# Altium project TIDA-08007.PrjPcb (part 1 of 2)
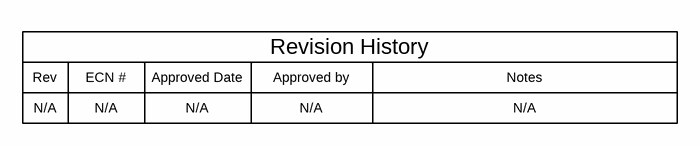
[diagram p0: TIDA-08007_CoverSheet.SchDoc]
CopyrightYear: 2019; PCB_Layout: Tessolve; PCB_Rev: A; PRJ_Customer: Public Release; PRJ_Engineer: Jake Pulliam; PRJ_Number: TIDA-080007; PRJ_Title: TIDA-080007; SCH_Rev: A; TechSupport: http://www.ti.com/support; TID: TIDA-080007
10 sheets, 292 parts. Net scope: flat (ports and power ports of the same name join across sheets).
Board file: TIDA-08007.PcbDoc
Sheets:
  TIDA-08007_CoverSheet.SchDoc
  TIDA-08007_DLPC230Interface.SchDoc
  TIDA-08007_VideoInterface.SchDoc
  TIDA-08007_DLPC230Power.SchDoc
  TIDA-08007_DLPC230GPIO.SchDoc
  TIDA-08007_DMDInterface.SchDoc
  TIDA-08007_DMDPower.SchDoc
  TIDA-08007_TPS99000Interface.SchDoc
  TIDA-08007_Power.SchDoc
  TIDA-08007_Hardware.SchDoc

## Sheet TIDA-08007_CoverSheet.SchDoc: Cover Page
size 431 x 279 mm; Date: Not shown in title block; ApprovedBy: Not shown in title block; CheckedBy: Not shown in title block; Author: Not shown in title block; CompanyName: Not shown in title block; DrawnBy: Jake Pulliam; Engineer: Jake Pulliam; Organization: Not shown in title block; Address1: Not shown in title block; Address2: Not shown in title block; Address3: Not shown in title block; Address4: Not shown in title block; DocumentNumber: 1; Revision: Use project parameter SCH_Rev; SheetNumber: 1; SheetTotal: 10; PageSetup: Record=PageOptions¦CenterHorizontal=True¦CenterVertical=True¦PrintScale=1.00¦XCorrection=1.00¦YCorrection=1.00¦PrintKind=0¦BorderSize=5000000¦LeftOffset=0¦BottomOffset=0¦Orientation=2¦PaperLength=1000¦PaperWidth=1000¦Scale=100¦PaperSource=15¦PrintQuality=600¦MediaType=1¦DitherType=10¦PaperKind=Letter¦PrintScaleMode=1

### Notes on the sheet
- Rev
- N/A
- ECN #
- Approved Date
- Approved by
- Revision History
- Notes

## Sheet TIDA-08007_DLPC230Interface.SchDoc: DLPC230 Host Interface
size 431 x 279 mm; Date: Not shown in title block; ApprovedBy: Not shown in title block; CheckedBy: Not shown in title block; Author: Not shown in title block; CompanyName: Not shown in title block; DrawnBy: Jake Pulliam; Engineer: Not shown in title block; Organization: Not shown in title block; Address1: Not shown in title block; Address2: Not shown in title block; Address3: Not shown in title block; Address4: Not shown in title block; DocumentNumber: 2; Revision: Use project parameter SCH_Rev; SheetNumber: 2; SheetTotal: 10; PageSetup: Record=PageOptions¦CenterHorizontal=True¦CenterVertical=True¦PrintScale=1.00¦XCorrection=1.00¦YCorrection=1.00¦PrintKind=0¦BorderSize=5000000¦LeftOffset=0¦BottomOffset=0¦Orientation=2¦PaperLength=1000¦PaperWidth=1000¦Scale=100¦PaperSource=15¦PrintQuality=600¦MediaType=1¦DitherType=10¦PaperKind=Letter¦PrintScaleMode=1
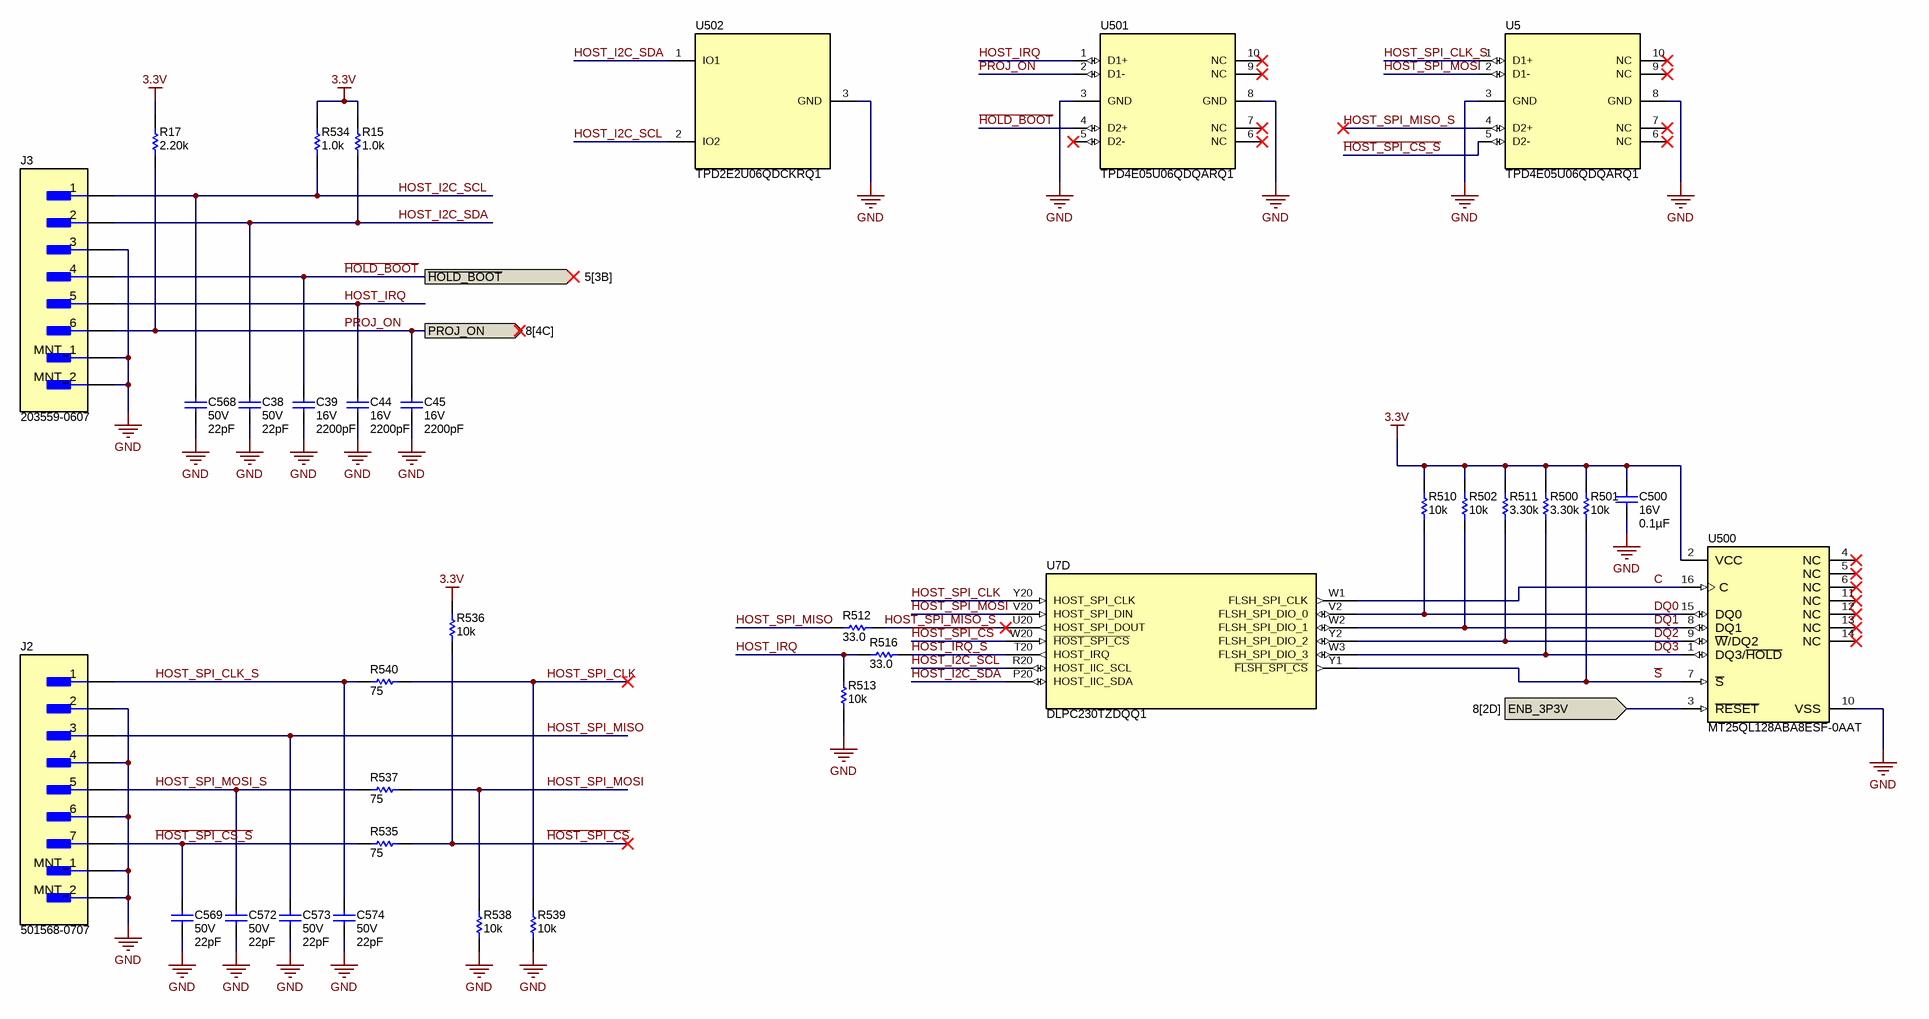
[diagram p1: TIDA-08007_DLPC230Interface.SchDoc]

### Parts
C38  VDC_V: 50V  ValueDisplayed: 22pF  [0402]  (hidden comment: CGA2B2NP01H220J050BA)
C39  VDC_V: 16V  ValueDisplayed: 2200pF  [0402]  (hidden comment: GRM155R71C222KA01D)
C44  VDC_V: 16V  ValueDisplayed: 2200pF  [0402]  (hidden comment: GRM155R71C222KA01D)
C45  VDC_V: 16V  ValueDisplayed: 2200pF  [0402]  (hidden comment: GRM155R71C222KA01D)
C500  VDC_V: 16V  ValueDisplayed: 0.1µF  [0402]  (hidden comment: GCM155R71C104JA55D)
C568  VDC_V: 50V  ValueDisplayed: 22pF  [0402]  (hidden comment: CGA2B2NP01H220J050BA)
C569  VDC_V: 50V  ValueDisplayed: 22pF  [0402]  (hidden comment: CGA2B2NP01H220J050BA)
C572  VDC_V: 50V  ValueDisplayed: 22pF  [0402]  (hidden comment: CGA2B2NP01H220J050BA)
C573  VDC_V: 50V  ValueDisplayed: 22pF  [0402]  (hidden comment: CGA2B2NP01H220J050BA)
C574  VDC_V: 50V  ValueDisplayed: 22pF  [0402]  (hidden comment: CGA2B2NP01H220J050BA)
J2  501568-0707  [FP-501568-0707_HDR7-MFG]
J3  203559-0607  [FP-203559-0607_HDR6-MFG]
R15  ValueDisplayed: 1.0k  [0402]  (hidden comment: ERJ-2GEJ102X)
R17  ValueDisplayed: 2.20k  [0402]  (hidden comment: ERJ-2RKF2201X)
R500  ValueDisplayed: 3.30k  [0402]  (hidden comment: ERJ-2RKF3301X)
R501  ValueDisplayed: 10k  [0402]  (hidden comment: ERJ-2GEJ103X)
R502  ValueDisplayed: 10k  [0402]  (hidden comment: ERJ-2GEJ103X)
R510  ValueDisplayed: 10k  [0402]  (hidden comment: ERJ-2GEJ103X)
R511  ValueDisplayed: 3.30k  [0402]  (hidden comment: ERJ-2RKF3301X)
R512  ValueDisplayed: 33.0  [0402]  (hidden comment: ERJ-2RKF33R0X)
R513  ValueDisplayed: 10k  [0402]  (hidden comment: ERJ-2GEJ103X)
R516  ValueDisplayed: 33.0  [0402]  (hidden comment: ERJ-2RKF33R0X)
R534  ValueDisplayed: 1.0k  [0402]  (hidden comment: ERJ-2GEJ102X)
R535  ValueDisplayed: 75  [0805_HV]  (hidden comment: ERJ-6GEYJ750V)
R536  ValueDisplayed: 10k  [0402]  (hidden comment: ERJ-2GEJ103X)
R537  ValueDisplayed: 75  [0805_HV]  (hidden comment: ERJ-6GEYJ750V)
R538  ValueDisplayed: 10k  [0402]  (hidden comment: ERJ-2GEJ103X)
R539  ValueDisplayed: 10k  [0402]  (hidden comment: ERJ-2GEJ103X)
R540  ValueDisplayed: 75  [0805_HV]  (hidden comment: ERJ-6GEYJ750V)
U5  TPD4E05U06QDQARQ1  [DQA0010A]
U7  DLPC230TZDQQ1  [ZDQ0324]  (part D of 9)
U500  MT25QL128ABA8ESF-0AAT  [FP-MT25QL128ABA8ESF-0AAT_SOP2-16-MFG]
U501  TPD4E05U06QDQARQ1  [DQA0010A]
U502  TPD2E2U06QDCKRQ1  [DCK0003A_N]

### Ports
ENB_3P3V (in, see 8[2D]), PROJ_ON (out, see 8[4C]), ~{HOLD_BOOT} (out, see 5[3B])

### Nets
3.3V: C500.1 R15.2 R17.2 R500.2 R501.2 R502.2 R510.2 R511.2 R534.2 R536.2 U500.2(VCC)
GND: C38.2 C39.2 C44.2 C45.2 C500.2 C568.2 C569.2 C572.2 C573.2 C574.2 J2.2 J2.4 J2.6 J2.8(MNT_1) J2.9(MNT_2) J3.3 J3.7(MNT_1) J3.8(MNT_2) R513.1 R538.1 R539.1 U5.3(GND) U5.8(GND) U500.10(VSS) U501.3(GND) U501.8(GND) U502.3(GND)
~{HOLD_BOOT}: C39.1 J3.4 U501.4(D2+) ; port ~{HOLD_BOOT}
~{HOST_SPI_CS}: R535.2 R536.1 U7.W20(~{HOST_SPI_CS})
~{HOST_SPI_CS_S}: C569.1 J2.7 R535.1 U5.5(D2-)
~{S}: R501.1 U7.Y1(~{FLSH_SPI_CS}) U500.7(~{S})
C: U7.W1(FLSH_SPI_CLK) U500.16(C)
DQ0: R510.1 U7.V2(FLSH_SPI_DIO_0) U500.15(DQ0)
DQ1: R502.1 U7.W2(FLSH_SPI_DIO_1) U500.8(DQ1)
DQ2: R511.1 U7.Y2(FLSH_SPI_DIO_2) U500.9(~{W}/DQ2)
DQ3: R500.1 U7.W3(FLSH_SPI_DIO_3) U500.1(DQ3/~{HOLD})
ENB_3P3V: U500.3(~{RESET}) ; port ENB_3P3V
HOST_I2C_SCL: C568.1 J3.1 R534.1 U7.R20(HOST_IIC_SCL) U502.2(IO2)
HOST_I2C_SDA: C38.1 J3.2 R15.1 U7.P20(HOST_IIC_SDA) U502.1(IO1)
HOST_IRQ: C44.1 J3.5 R513.2 R516.1 U501.1(D1+)
HOST_IRQ_S: R516.2 U7.T20(HOST_IRQ)
HOST_SPI_CLK: R539.2 R540.2 U7.Y20(HOST_SPI_CLK)
HOST_SPI_CLK_S: C574.1 J2.1 R540.1 U5.1(D1+)
HOST_SPI_MISO: C573.1 J2.3 R512.1
HOST_SPI_MISO_S: R512.2 U5.4(D2+) U7.U20(HOST_SPI_DOUT)
HOST_SPI_MOSI: R537.2 R538.2 U5.2(D1-) U7.V20(HOST_SPI_DIN)
HOST_SPI_MOSI_S: C572.1 J2.5 R537.1
PROJ_ON: C45.1 J3.6 R17.1 U501.2(D1-) ; port PROJ_ON

Not connected (* = marked no-connect by the designer): U5 6(NC)* 7(NC)* 9(NC)* 10(NC)*; U500 4(NC)* 5(NC)* 6(NC)* 11(NC)* 12(NC)* 13(NC)* 14(NC)*; U501 5(D2-)* 6(NC)* 7(NC)* 9(NC)* 10(NC)*

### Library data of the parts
C38 C568 C569 C572-C574 = CMP-0006311-2: CAP, CERM, 22 pF, 50 V, +/- 5%, C0G/NP0, AEC-Q200 Grade 1, 0402; Manufacturer: TDK; TaMin_C: -55°C; Polarized: N; SizeAreaWB_mm2: 3; Value1: Unknown; U/M: EA; Value: 22pF; TaMax_C: 125°C; SizeZ_mm: 0.6; SizeX_mm: 1; SizeY_mm: 0.5; AEC Qualified: Y; AEC Category: Q200
C39 C44 C45 = CMP-0006646-2: CAP, CERM, 2200 pF, 16 V, +/- 10%, X7R, 0402; Manufacturer: MuRata; TaMin_C: -55°C; Polarized: N; SizeAreaWB_mm2: 3; Value1: Unknown; U/M: EA; Value: 2200pF; TaMax_C: 125°C; SizeZ_mm: 0.6; SizeX_mm: 1; SizeY_mm: 0.5; Cap_F: 2.2nF; AEC Category: Q200
C500 = CMP-0080702-1: CAP, CERM, 0.1 µF, 16 V,+/- 5%, X7R, AEC-Q200 Grade 1, 0402; Manufacturer: MuRata; Cap_F: 100nF; SizeAreaWB_mm2: 3; SizeArea_mm2: 0.5; AEC Qualified: Y; AEC Category: Q200; Value: 0.1uF; TaMax_C: 125°C; SizeZ_mm: 0.6; AEC Grade: 1; Polarized: N; TaMin_C: -55°C; U/M: EA
J2 = CMP-0087313-1: CONN HEADER 1MM 7POS SMD R/A; Manufacturer: Molex; Voltage_V: 50V; Row_Count: 1; ContactFinish: Tin,Nickel; Current_A: 1A
J3 = CMP-0087314-1: CONN HEADER SMD R/A 6POS 1MM; Manufacturer: Molex; Current_A: 1A; Row_Count: 1; Voltage_V: 50V; ContactFinish: Gold,Nickel
R15 R534 = CMP-0078193-1: RES, 1.0 k, 5%, 0.1 W, AEC-Q200 Grade 0, 0402; Manufacturer: Panasonic; Value_Code: 1k00; SizeArea_mm2: 0.5; AEC Qualified: Y; AEC Category: Q200; Res_ohm: 1k; Value: 1.0k; SizeZ_mm: 0.6; Green_REACh: Passed; EIA_Code: E24; TempCo: 200 ppm/C; AEC Grade: 0; Power_W: 100mW; VDC_V: 50V; Value2: 0.1W; Green_Lifecycle: Active; U/M: EA; SizeX_mm: 1
R17 = CMP-0026681-1: RES, 2.20 k, 1%, 0.1 W, 0402; Manufacturer: Panasonic; Power_W: 100mW; TempCo: 100 ppm/C; Value_Code: 2k20; U/M: EA; Value: 2.20k; Res_ohm: 2.2k; SizeX_mm: 1; SizeY_mm: 0.5; SizeZ_mm: 0.6; Value2: 0.1W; VDC_V: 50V; AEC Category: Q200
R500 R511 = CMP-0026695-1: RES, 3.30 k, 1%, 0.1 W, AEC-Q200 Grade 0, 0402; Manufacturer: Panasonic; Power_W: 100mW; TempCo: 100 ppm/C; Value_Code: 3k30; U/M: EA; Value: 3.30k; Res_ohm: 3.3k; SizeX_mm: 1; SizeY_mm: 0.5; SizeZ_mm: 0.6; Value2: 0.1W; AEC Qualified: Y; VDC_V: 50V; AEC Grade: 0; AEC Category: Q200
R501 R502 R510 R513 R536 R538 R539 = CMP-0026994-4: RES, 10 k, 5%, 0.1 W, AEC-Q200 Grade 0, 0402; Manufacturer: Panasonic; Power_W: 100mW; TempCo: 200 ppm/C; Value_Code: 10k0; U/M: EA; Value: 10k; EIA_Code: E24; SizeX_mm: 1; SizeY_mm: 0.5; SizeZ_mm: 0.6; Value2: 0.1W; AEC Qualified: Y; VDC_V: 50V; AEC Grade: 0; AEC Category: Q200
R512 R516 = CMP-0026696-1: RES, 33.0, 1%, 0.1 W, 0402; Manufacturer: Panasonic; Power_W: 100mW; TempCo: 100 ppm/C; Value_Code: 33R0; U/M: EA; Value: 33.0; Res_ohm: 33; SizeX_mm: 1; SizeY_mm: 0.5; SizeZ_mm: 0.6; Value2: 0.1W; VDC_V: 50V; AEC Category: Q200
R535 R537 R540 = CMP-0020766-3: RES, 75, 5%, 0.125 W, AEC-Q200 Grade 0, 0805; Manufacturer: Panasonic; Power_W: 125mW; TempCo: 200 ppm/C; Value_Code: 75R0; Value: 75; EIA_Code: E24; SizeX_mm: 2; SizeY_mm: 1.25; SizeZ_mm: 1.45; Value2: 0.125W; SizeArea_mm2: 2.5; AEC Qualified: Y; VDC_V: 150V; AEC Category: Q200; AEC Grade: 0; SizeAreaWB_mm2: 6.75
U5 U501 = CMP-0073599-3: Automotive 4-Channel ESD Protection Solution for SuperSpeed (up to 5 Gbps) Interface, DQA0010A (USON-10); Manufacturer: Texas Instruments; SizeZ_mm: 0.55; SizeX_mm: 1.0; SizeY_mm: 2.5; CompType: IC; SizeAreaWB_mm2: 7.0; AEC Category: Q200; AEC Qualified: Y
U7 = CMP-0750177-3: DLP® Automotive DMD Controller for DLP553x-Q1 Chipset, ZDQ0324 (BGA-324); Manufacturer: Texas Instruments; SizeAreaWB_mm2: 625; SizeArea_mm2: 529; SizeX_mm: 23; AEC Qualified: Y; CompType: IC; AEC Category: Q200; SizeZ_mm: 2.352
U500 = CMP-0086504-1: FLASH - NOR Memory IC 128Mb (16M x 8) SPI 133MHz  16-SOP2; Manufacturer: Micron; SizeZ_mm: 2.65mm
U502 = CMP-0073595-1: Automotive Dual-Channel High-Speed ESD Protection Device, DCK0003A (SOT-SC70-3); Alternate Manufacturer: Texas Instruments; SizeAreaWB_mm2: 9.3; U/M: EA; SizeZ_mm: 1.1; SizeX_mm: 2.1; SizeY_mm: 2.0; SizeArea_mm2: 4.2; CompType: IC

## Sheet TIDA-08007_VideoInterface.SchDoc: DLPC230 OpenLDI Interface
size 431 x 279 mm; Date: Not shown in title block; ApprovedBy: Not shown in title block; CheckedBy: Not shown in title block; Author: Not shown in title block; CompanyName: Not shown in title block; DrawnBy: Jake Pulliam; Engineer: Not shown in title block; Organization: Not shown in title block; Address1: Not shown in title block; Address2: Not shown in title block; Address3: Not shown in title block; Address4: Not shown in title block; DocumentNumber: 3; Revision: Use project parameter SCH_Rev; SheetNumber: 3; SheetTotal: 10; PageSetup: Record=PageOptions¦CenterHorizontal=True¦CenterVertical=True¦PrintScale=1.00¦XCorrection=1.00¦YCorrection=1.00¦PrintKind=0¦BorderSize=5000000¦LeftOffset=0¦BottomOffset=0¦Orientation=2¦PaperLength=1000¦PaperWidth=1000¦Scale=100¦PaperSource=15¦PrintQuality=600¦MediaType=1¦DitherType=10¦PaperKind=Letter¦PrintScaleMode=1
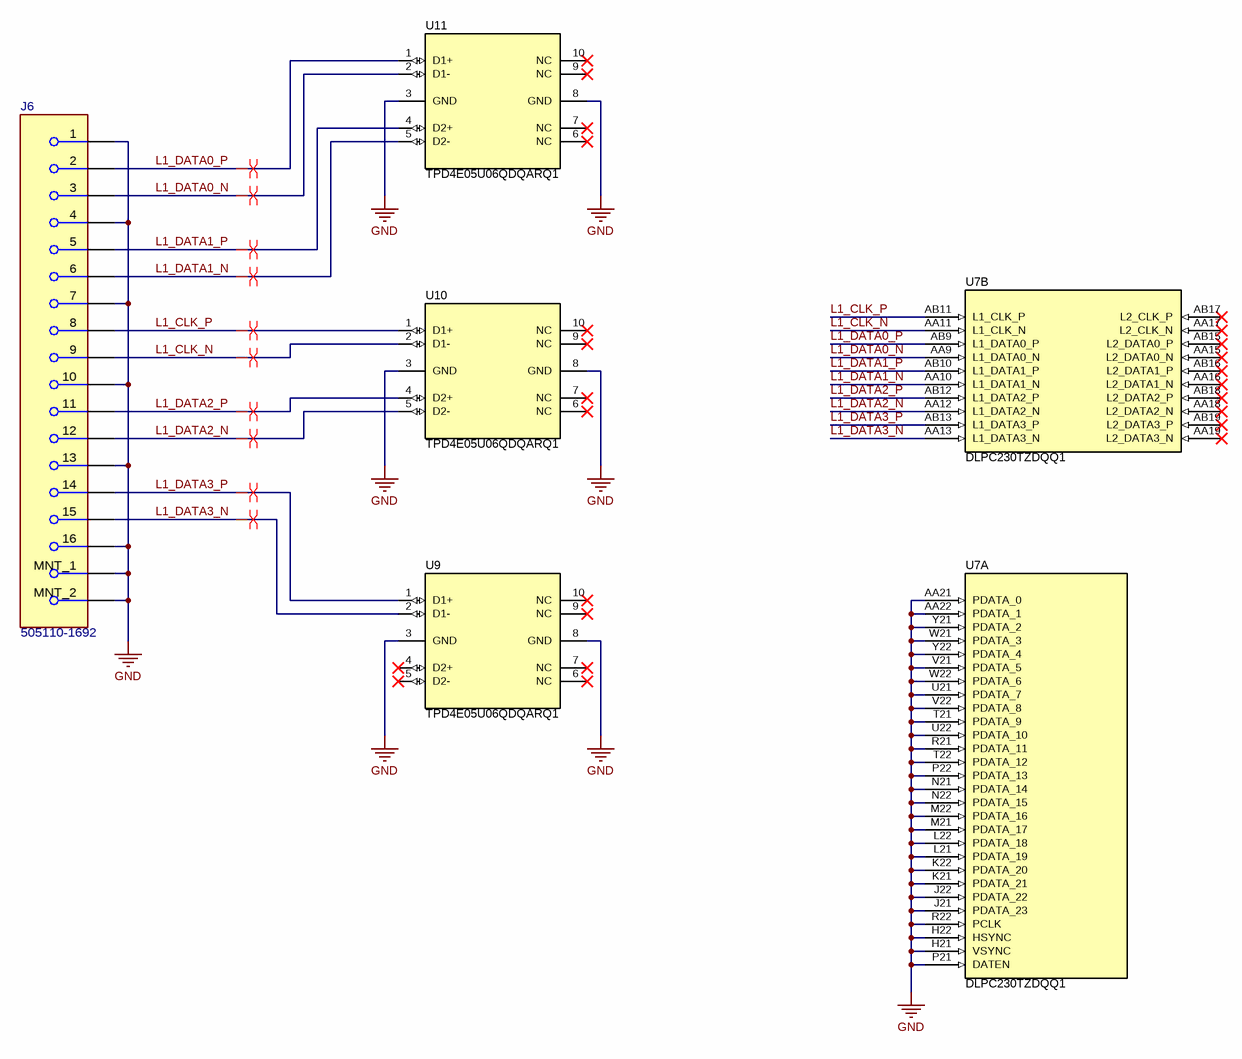
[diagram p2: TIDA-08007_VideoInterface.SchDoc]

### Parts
J6  505110-1692  [FP-505110-1692_CONN_SMT_12MM7_5MM25-MFG]
U7  DLPC230TZDQQ1  [ZDQ0324]  (parts A,B of 9)
U9  TPD4E05U06QDQARQ1  [DQA0010A]
U10  TPD4E05U06QDQARQ1  [DQA0010A]
U11  TPD4E05U06QDQARQ1  [DQA0010A]

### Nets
GND: J6.1 J6.4 J6.7 J6.10 J6.13 J6.16 J6.17(MNT_1) J6.18(MNT_2) U7.AA21(PDATA_0) U7.AA22(PDATA_1) U7.H21(VSYNC) U7.H22(HSYNC) U7.J21(PDATA_23) U7.J22(PDATA_22) U7.K21(PDATA_21) U7.K22(PDATA_20) U7.L21(PDATA_19) U7.L22(PDATA_18) U7.M21(PDATA_17) U7.M22(PDATA_16) U7.N21(PDATA_14) U7.N22(PDATA_15) U7.P21(DATEN) U7.P22(PDATA_13) U7.R21(PDATA_11) U7.R22(PCLK) U7.T21(PDATA_9) U7.T22(PDATA_12) U7.U21(PDATA_7) U7.U22(PDATA_10) U7.V21(PDATA_5) U7.V22(PDATA_8) U7.W21(PDATA_3) U7.W22(PDATA_6) U7.Y21(PDATA_2) U7.Y22(PDATA_4) U9.3(GND) U9.8(GND) U10.3(GND) U10.8(GND) U11.3(GND) U11.8(GND)
L1_CLK_N: J6.9 U7.AA11(L1_CLK_N) U10.2(D1-)
L1_CLK_P: J6.8 U7.AB11(L1_CLK_P) U10.1(D1+)
L1_DATA0_N: J6.3 U7.AA9(L1_DATA0_N) U11.2(D1-)
L1_DATA0_P: J6.2 U7.AB9(L1_DATA0_P) U11.1(D1+)
L1_DATA1_N: J6.6 U7.AA10(L1_DATA1_N) U11.5(D2-)
L1_DATA1_P: J6.5 U7.AB10(L1_DATA1_P) U11.4(D2+)
L1_DATA2_N: J6.12 U7.AA12(L1_DATA2_N) U10.5(D2-)
L1_DATA2_P: J6.11 U7.AB12(L1_DATA2_P) U10.4(D2+)
L1_DATA3_N: J6.15 U7.AA13(L1_DATA3_N) U9.2(D1-)
L1_DATA3_P: J6.14 U7.AB13(L1_DATA3_P) U9.1(D1+)

Not connected (* = marked no-connect by the designer): U7 AA15(L2_DATA0_N)* AA16(L2_DATA1_N)* AA17(L2_CLK_N)* AA18(L2_DATA2_N)* AA19(L2_DATA3_N)* AB15(L2_DATA0_P)* AB16(L2_DATA1_P)* AB17(L2_CLK_P)* AB18(L2_DATA2_P)* AB19(L2_DATA3_P)*; U9 4(D2+)* 5(D2-)* 6(NC)* 7(NC)* 9(NC)* 10(NC)*; U10 6(NC)* 7(NC)* 9(NC)* 10(NC)*; U11 6(NC)* 7(NC)* 9(NC)* 10(NC)*

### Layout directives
differential pair: L1_CLK_N, L1_CLK_P, L1_DATA0_N, L1_DATA0_P, L1_DATA1_N, L1_DATA1_P, L1_DATA2_N, L1_DATA2_P, L1_DATA3_N, L1_DATA3_P

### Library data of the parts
J6 = CMP-0086503-1: CONN FPC BOTTOM 16POS .5MM R/A; Manufacturer: Molex; Voltage_V: 50V; Current_A: 500mA; ContactFinish: Gold,Nickel
U7 = CMP-0750177-3: as U7 on sheet TIDA-08007_DLPC230Interface
U9-U11 = CMP-0073599-3: as U5 on sheet TIDA-08007_DLPC230Interface

## Sheet TIDA-08007_DLPC230Power.SchDoc: DLPC230 Power and Clock
size 431 x 279 mm; Date: Not shown in title block; ApprovedBy: Not shown in title block; CheckedBy: Not shown in title block; Author: Not shown in title block; CompanyName: Not shown in title block; DrawnBy: Jake Pulliam; Engineer: Not shown in title block; Organization: Not shown in title block; Address1: Not shown in title block; Address2: Not shown in title block; Address3: Not shown in title block; Address4: Not shown in title block; DocumentNumber: 4; Revision: Use project parameter SCH_Rev; SheetNumber: 4; SheetTotal: 10; PageSetup: Record=PageOptions¦CenterHorizontal=True¦CenterVertical=True¦PrintScale=1.00¦XCorrection=1.00¦YCorrection=1.00¦PrintKind=0¦BorderSize=5000000¦LeftOffset=0¦BottomOffset=0¦Orientation=2¦PaperLength=1000¦PaperWidth=1000¦Scale=100¦PaperSource=15¦PrintQuality=600¦MediaType=1¦DitherType=10¦PaperKind=Letter¦PrintScaleMode=1
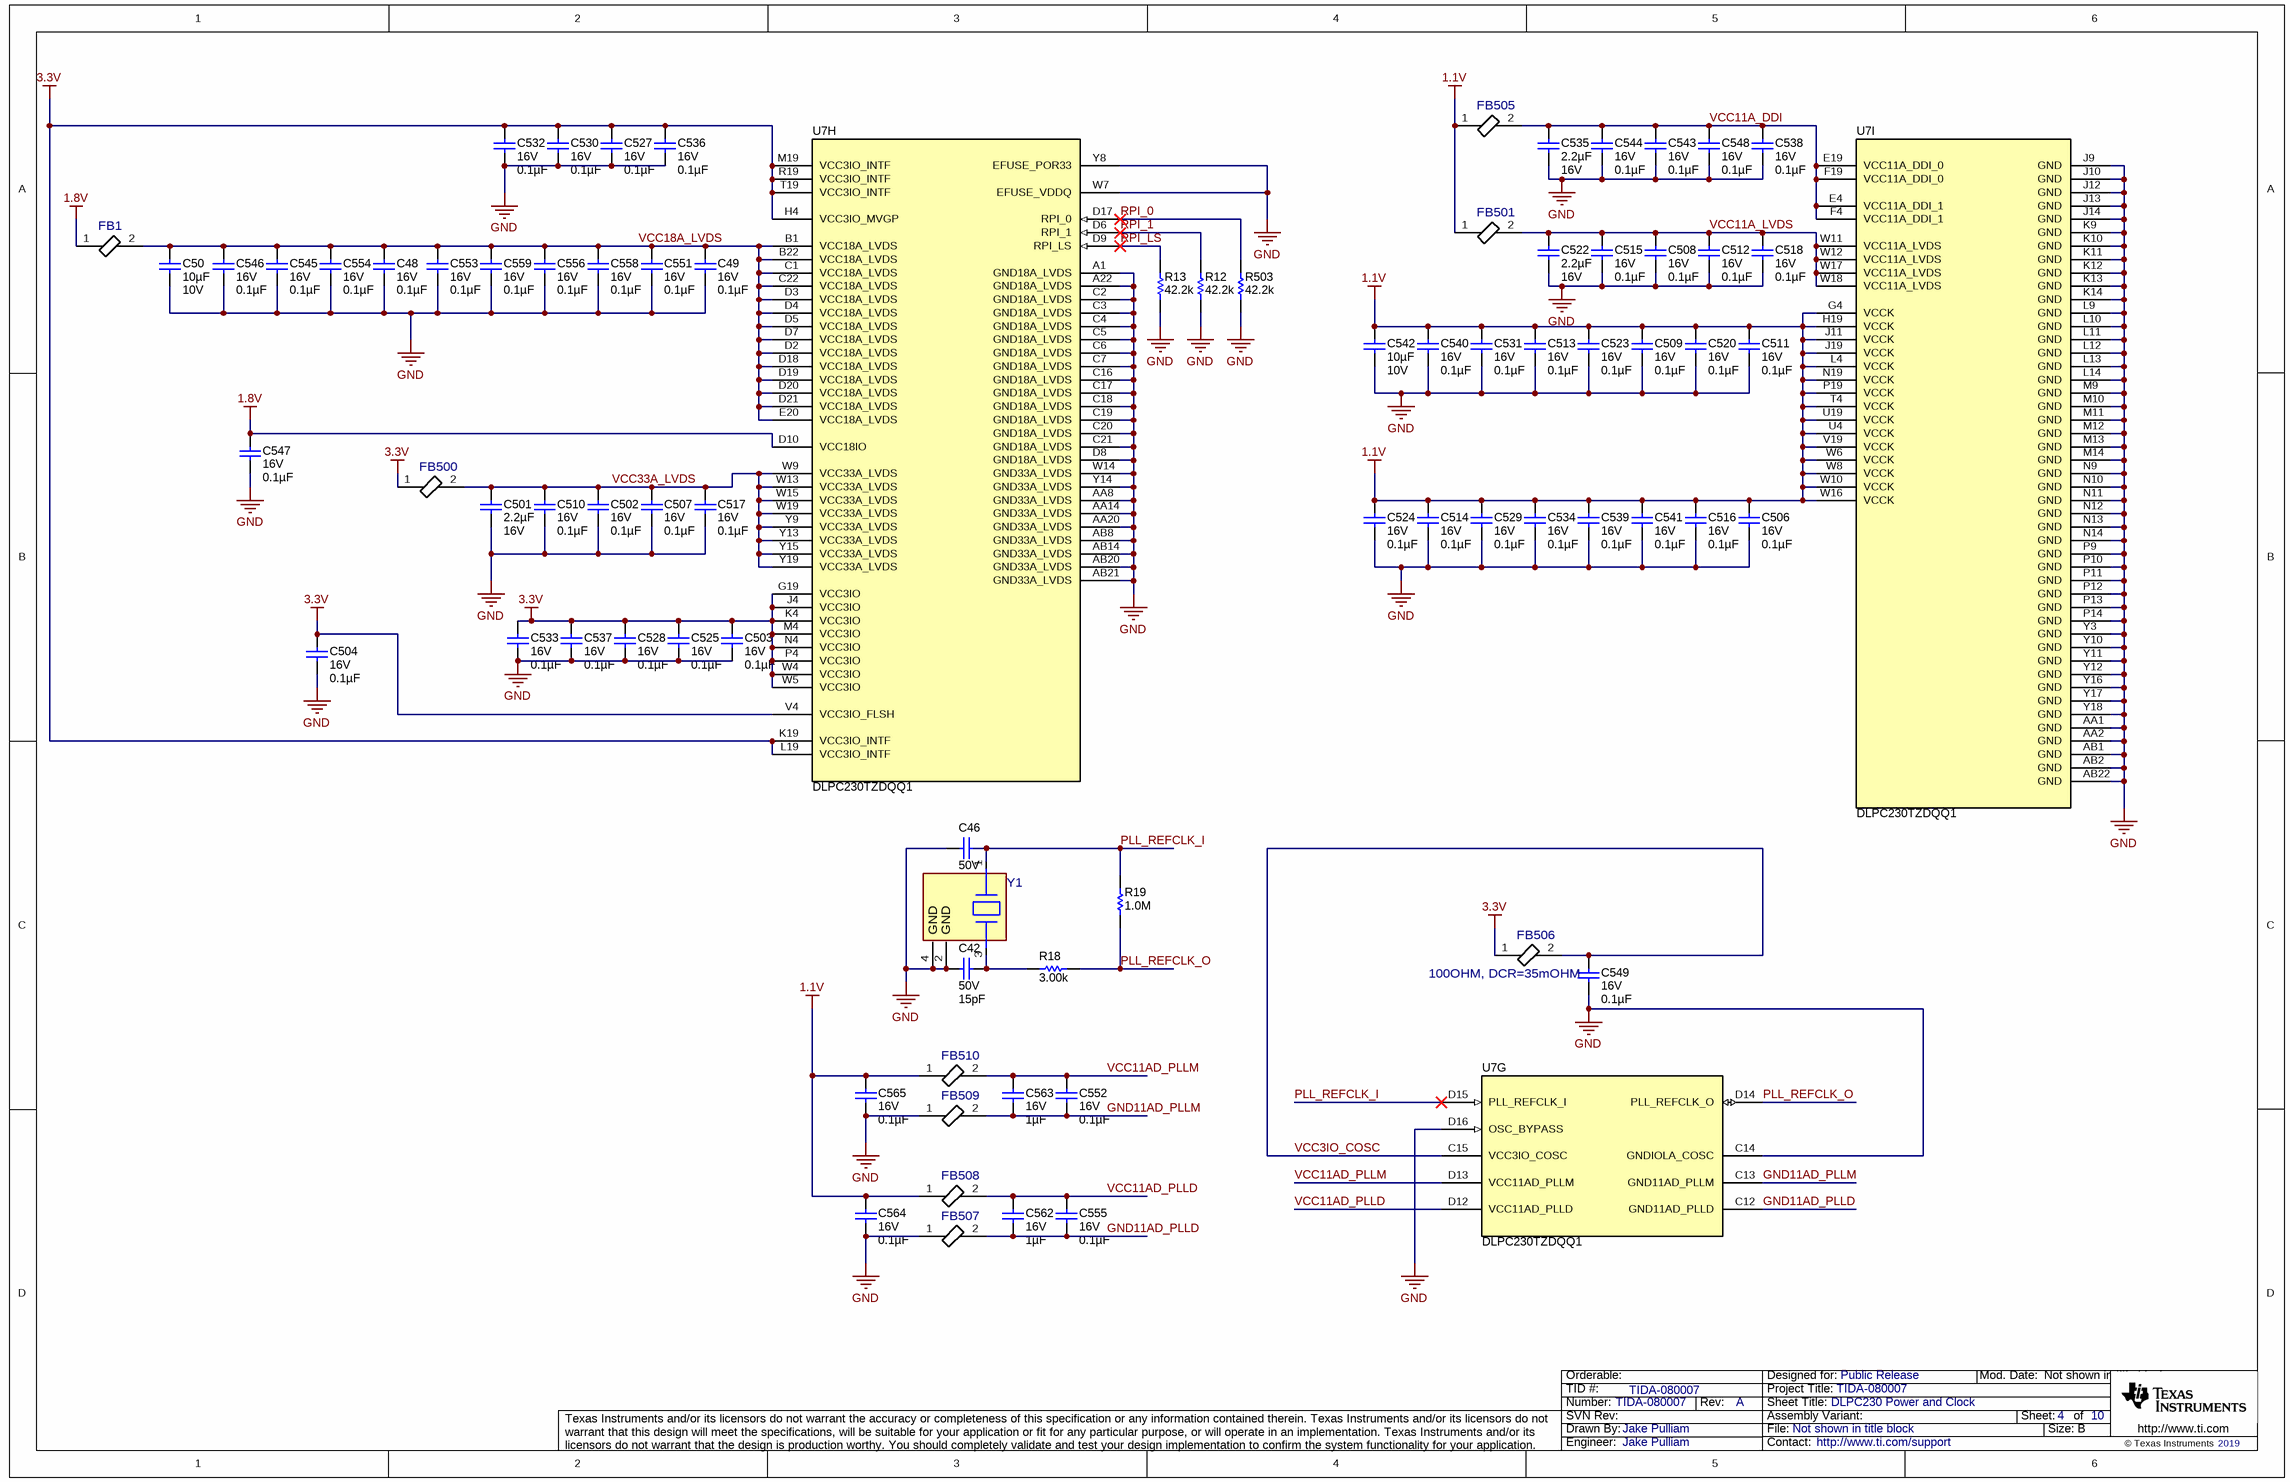
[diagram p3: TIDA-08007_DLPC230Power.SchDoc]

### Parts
C42  VDC_V: 50V  ValueDisplayed: 15pF  [0603]  (hidden comment: GCM1885C1H150JA16D)
C46  VDC_V: 50V  ValueDisplayed: 15pF  [0603]  (hidden comment: GCM1885C1H150JA16D)
C48  VDC_V: 16V  ValueDisplayed: 0.1µF  [0402]  (hidden comment: GCM155R71C104JA55D)
C49  VDC_V: 16V  ValueDisplayed: 0.1µF  [0402]  (hidden comment: GCM155R71C104JA55D)
C50  Cap_F: 10µF  VDC_V: 10V  [0805_HV]  (hidden comment: C2012X7R1A106M125AC)
C501  Cap_F: 2.2µF  VDC_V: 16V  [0603]  (hidden comment: EMK107BB7225MA-T)
C502  VDC_V: 16V  ValueDisplayed: 0.1µF  [0402]  (hidden comment: GCM155R71C104JA55D)
C503  VDC_V: 16V  ValueDisplayed: 0.1µF  [0402]  (hidden comment: GCM155R71C104JA55D)
C504  VDC_V: 16V  ValueDisplayed: 0.1µF  [0402]  (hidden comment: GCM155R71C104JA55D)
C506  VDC_V: 16V  ValueDisplayed: 0.1µF  [0402]  (hidden comment: GCM155R71C104JA55D)
C507  VDC_V: 16V  ValueDisplayed: 0.1µF  [0402]  (hidden comment: GCM155R71C104JA55D)
C508  VDC_V: 16V  ValueDisplayed: 0.1µF  [0402]  (hidden comment: GCM155R71C104JA55D)
C509  VDC_V: 16V  ValueDisplayed: 0.1µF  [0402]  (hidden comment: GCM155R71C104JA55D)
C510  VDC_V: 16V  ValueDisplayed: 0.1µF  [0402]  (hidden comment: GCM155R71C104JA55D)
C511  VDC_V: 16V  ValueDisplayed: 0.1µF  [0402]  (hidden comment: GCM155R71C104JA55D)
C512  VDC_V: 16V  ValueDisplayed: 0.1µF  [0402]  (hidden comment: GCM155R71C104JA55D)
C513  VDC_V: 16V  ValueDisplayed: 0.1µF  [0402]  (hidden comment: GCM155R71C104JA55D)
C514  VDC_V: 16V  ValueDisplayed: 0.1µF  [0402]  (hidden comment: GCM155R71C104JA55D)
C515  VDC_V: 16V  ValueDisplayed: 0.1µF  [0402]  (hidden comment: GCM155R71C104JA55D)
C516  VDC_V: 16V  ValueDisplayed: 0.1µF  [0402]  (hidden comment: GCM155R71C104JA55D)
C517  VDC_V: 16V  ValueDisplayed: 0.1µF  [0402]  (hidden comment: GCM155R71C104JA55D)
C518  VDC_V: 16V  ValueDisplayed: 0.1µF  [0402]  (hidden comment: GCM155R71C104JA55D)
C520  VDC_V: 16V  ValueDisplayed: 0.1µF  [0402]  (hidden comment: GCM155R71C104JA55D)
C522  Cap_F: 2.2µF  VDC_V: 16V  [0603]  (hidden comment: EMK107BB7225MA-T)
C523  VDC_V: 16V  ValueDisplayed: 0.1µF  [0402]  (hidden comment: GCM155R71C104JA55D)
C524  VDC_V: 16V  ValueDisplayed: 0.1µF  [0402]  (hidden comment: GCM155R71C104JA55D)
C525  VDC_V: 16V  ValueDisplayed: 0.1µF  [0402]  (hidden comment: GCM155R71C104JA55D)
C527  VDC_V: 16V  ValueDisplayed: 0.1µF  [0402]  (hidden comment: GCM155R71C104JA55D)
C528  VDC_V: 16V  ValueDisplayed: 0.1µF  [0402]  (hidden comment: GCM155R71C104JA55D)
C529  VDC_V: 16V  ValueDisplayed: 0.1µF  [0402]  (hidden comment: GCM155R71C104JA55D)
C530  VDC_V: 16V  ValueDisplayed: 0.1µF  [0402]  (hidden comment: GCM155R71C104JA55D)
C531  VDC_V: 16V  ValueDisplayed: 0.1µF  [0402]  (hidden comment: GCM155R71C104JA55D)
C532  VDC_V: 16V  ValueDisplayed: 0.1µF  [0402]  (hidden comment: GCM155R71C104JA55D)
C533  VDC_V: 16V  ValueDisplayed: 0.1µF  [0402]  (hidden comment: GCM155R71C104JA55D)
C534  VDC_V: 16V  ValueDisplayed: 0.1µF  [0402]  (hidden comment: GCM155R71C104JA55D)
C535  Cap_F: 2.2µF  VDC_V: 16V  [0603]  (hidden comment: EMK107BB7225MA-T)
C536  VDC_V: 16V  ValueDisplayed: 0.1µF  [0402]  (hidden comment: GCM155R71C104JA55D)
C537  VDC_V: 16V  ValueDisplayed: 0.1µF  [0402]  (hidden comment: GCM155R71C104JA55D)
C538  VDC_V: 16V  ValueDisplayed: 0.1µF  [0402]  (hidden comment: GCM155R71C104JA55D)
C539  VDC_V: 16V  ValueDisplayed: 0.1µF  [0402]  (hidden comment: GCM155R71C104JA55D)
C540  VDC_V: 16V  ValueDisplayed: 0.1µF  [0402]  (hidden comment: GCM155R71C104JA55D)
C541  VDC_V: 16V  ValueDisplayed: 0.1µF  [0402]  (hidden comment: GCM155R71C104JA55D)
C542  Cap_F: 10µF  VDC_V: 10V  [0805_HV]  (hidden comment: C2012X7R1A106M125AC)
C543  VDC_V: 16V  ValueDisplayed: 0.1µF  [0402]  (hidden comment: GCM155R71C104JA55D)
C544  VDC_V: 16V  ValueDisplayed: 0.1µF  [0402]  (hidden comment: GCM155R71C104JA55D)
C545  VDC_V: 16V  ValueDisplayed: 0.1µF  [0402]  (hidden comment: GCM155R71C104JA55D)
C546  VDC_V: 16V  ValueDisplayed: 0.1µF  [0402]  (hidden comment: GCM155R71C104JA55D)
C547  VDC_V: 16V  ValueDisplayed: 0.1µF  [0402]  (hidden comment: GCM155R71C104JA55D)
C548  VDC_V: 16V  ValueDisplayed: 0.1µF  [0402]  (hidden comment: GCM155R71C104JA55D)
C549  VDC_V: 16V  ValueDisplayed: 0.1µF  [0402]  (hidden comment: GCM155R71C104JA55D)
C551  VDC_V: 16V  ValueDisplayed: 0.1µF  [0402]  (hidden comment: GCM155R71C104JA55D)
C552  VDC_V: 16V  ValueDisplayed: 0.1µF  [0402]  (hidden comment: GCM155R71C104JA55D)
C553  VDC_V: 16V  ValueDisplayed: 0.1µF  [0402]  (hidden comment: GCM155R71C104JA55D)
C554  VDC_V: 16V  ValueDisplayed: 0.1µF  [0402]  (hidden comment: GCM155R71C104JA55D)
C555  VDC_V: 16V  ValueDisplayed: 0.1µF  [0402]  (hidden comment: GCM155R71C104JA55D)
C556  VDC_V: 16V  ValueDisplayed: 0.1µF  [0402]  (hidden comment: GCM155R71C104JA55D)
C558  VDC_V: 16V  ValueDisplayed: 0.1µF  [0402]  (hidden comment: GCM155R71C104JA55D)
C559  VDC_V: 16V  ValueDisplayed: 0.1µF  [0402]  (hidden comment: GCM155R71C104JA55D)
C562  VDC_V: 16V  Cap_F: 1µF  [0805_HV]  (hidden comment: GCM219R71C105KA37D)
C563  VDC_V: 16V  Cap_F: 1µF  [0805_HV]  (hidden comment: GCM219R71C105KA37D)
C564  VDC_V: 16V  ValueDisplayed: 0.1µF  [0402]  (hidden comment: GCM155R71C104JA55D)
C565  VDC_V: 16V  ValueDisplayed: 0.1µF  [0402]  (hidden comment: GCM155R71C104JA55D)
FB1  FBMH1608HM101-TV  [FP-FBMH1608HM101-TV_0603-MFG]  (value not drawn)
FB500  FBMH1608HM101-TV  [FP-FBMH1608HM101-TV_0603-MFG]  (value not drawn)
FB501  FBMH1608HM101-TV  [FP-FBMH1608HM101-TV_0603-MFG]  (value not drawn)
FB505  FBMH1608HM101-TV  [FP-FBMH1608HM101-TV_0603-MFG]  (value not drawn)
FB506  100OHM, DCR=35mOHM  [FP-FBMH1608HM101-TV_0603-MFG]
FB507  FBMH1608HM101-TV  [FP-FBMH1608HM101-TV_0603-MFG]  (value not drawn)
FB508  FBMH1608HM101-TV  [FP-FBMH1608HM101-TV_0603-MFG]  (value not drawn)
FB509  FBMH1608HM101-TV  [FP-FBMH1608HM101-TV_0603-MFG]  (value not drawn)
FB510  FBMH1608HM101-TV  [FP-FBMH1608HM101-TV_0603-MFG]  (value not drawn)
R12  ValueDisplayed: 42.2k  [0805_HV]  (hidden comment: ERJ-6ENF4222V)
R13  ValueDisplayed: 42.2k  [0805_HV]  (hidden comment: ERJ-6ENF4222V)
R18  ValueDisplayed: 3.00k  [0805_HV]  (hidden comment: ERJ-6ENF3001V)
R19  ValueDisplayed: 1.0M  [0805_HV]  (hidden comment: ERJ-6GEYJ105V)
R503  ValueDisplayed: 42.2k  [0805_HV]  (hidden comment: ERJ-6ENF4222V)
U7  DLPC230TZDQQ1  [ZDQ0324]  (parts G,H,I of 9)
Y1  AM16070006  [FP-AM16070006_SMT_XTAL_3MM2_2MM5-MFG]  (value not drawn)

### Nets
1.1V: C506.1 C509.1 C511.1 C513.1 C514.1 C516.1 C520.1 C523.1 C524.1 C529.1 C531.1 C534.1 C539.1 C540.1 C541.1 C542.1 C564.1 C565.1 FB501.1 FB505.1 FB508.1 FB510.1 U7.G4(VCCK) U7.H19(VCCK) U7.J11(VCCK) U7.J19(VCCK) U7.L4(VCCK) U7.N19(VCCK) U7.P19(VCCK) U7.T4(VCCK) U7.U4(VCCK) U7.U19(VCCK) U7.V19(VCCK) U7.W6(VCCK) U7.W8(VCCK) U7.W10(VCCK) U7.W16(VCCK)
1.8V: C547.1 FB1.1 U7.D10(VCC18IO)
3.3V: C503.1 C504.1 C525.1 C527.1 C528.1 C530.1 C532.1 C533.1 C536.1 C537.1 FB500.1 FB506.1 U7.G19(VCC3IO) U7.H4(VCC3IO_MVGP) U7.J4(VCC3IO) U7.K4(VCC3IO) U7.K19(VCC3IO_INTF) U7.L19(VCC3IO_INTF) U7.M4(VCC3IO) U7.M19(VCC3IO_INTF) U7.N4(VCC3IO) U7.P4(VCC3IO) U7.R19(VCC3IO_INTF) U7.T19(VCC3IO_INTF) U7.V4(VCC3IO_FLSH) U7.W4(VCC3IO) U7.W5(VCC3IO)
GND: C42.2 C46.2 C48.2 C49.2 C50.2 C501.2 C502.2 C503.2 C504.2 C506.2 C507.2 C508.2 C509.2 C510.2 C511.2 C512.2 C513.2 C514.2 C515.2 C516.2 C517.2 C518.2 C520.2 C522.2 C523.2 C524.2 C525.2 C527.2 C528.2 C529.2 C530.2 C531.2 C532.2 C533.2 C534.2 C535.2 C536.2 C537.2 C538.2 C539.2 C540.2 C541.2 C542.2 C543.2 C544.2 C545.2 C546.2 C547.2 C548.2 C549.2 C551.2 C553.2 C554.2 C556.2 C558.2 C559.2 C564.2 C565.2 FB507.1 FB509.1 R12.1 R13.1 R503.1 U7.A1(GND18A_LVDS) U7.A22(GND18A_LVDS) U7.AA1(GND) U7.AA2(GND) U7.AA8(GND33A_LVDS) U7.AA14(GND33A_LVDS) U7.AA20(GND33A_LVDS) U7.AB1(GND) U7.AB2(GND) U7.AB8(GND33A_LVDS) U7.AB14(GND33A_LVDS) U7.AB20(GND33A_LVDS) U7.AB21(GND33A_LVDS) U7.AB22(GND) U7.C2(GND18A_LVDS) U7.C3(GND18A_LVDS) U7.C4(GND18A_LVDS) U7.C5(GND18A_LVDS) U7.C6(GND18A_LVDS) U7.C7(GND18A_LVDS) U7.C14(GNDIOLA_COSC) U7.C16(GND18A_LVDS) U7.C17(GND18A_LVDS) U7.C18(GND18A_LVDS) U7.C19(GND18A_LVDS) U7.C20(GND18A_LVDS) U7.C21(GND18A_LVDS) U7.D8(GND18A_LVDS) U7.D16(OSC_BYPASS) U7.J9(GND) U7.J10(GND) U7.J12(GND) U7.J13(GND) U7.J14(GND) U7.K9(GND) U7.K10(GND) U7.K11(GND) U7.K12(GND) U7.K13(GND) U7.K14(GND) U7.L9(GND) U7.L10(GND) U7.L11(GND) U7.L12(GND) U7.L13(GND) U7.L14(GND) U7.M9(GND) U7.M10(GND) U7.M11(GND) U7.M12(GND) U7.M13(GND) U7.M14(GND) U7.N9(GND) U7.N10(GND) U7.N11(GND) U7.N12(GND) U7.N13(GND) U7.N14(GND) U7.P9(GND) U7.P10(GND) U7.P11(GND) U7.P12(GND) U7.P13(GND) U7.P14(GND) U7.W7(EFUSE_VDDQ) U7.W14(GND33A_LVDS) U7.Y3(GND) U7.Y8(EFUSE_POR33) U7.Y10(GND) U7.Y11(GND) U7.Y12(GND) U7.Y14(GND33A_LVDS) U7.Y16(GND) U7.Y17(GND) U7.Y18(GND) Y1.2(GND) Y1.4(GND)
GND11AD_PLLD: C555.2 C562.2 FB507.2 U7.C12(GND11AD_PLLD)
GND11AD_PLLM: C552.2 C563.2 FB509.2 U7.C13(GND11AD_PLLM)
PLL_REFCLK_I: C46.1 R19.2 U7.D15(PLL_REFCLK_I) Y1.1
PLL_REFCLK_O: R18.2 R19.1 U7.D14(PLL_REFCLK_O)
RPI_0: R503.2 U7.D17(RPI_0)
RPI_1: R12.2 U7.D6(RPI_1)
RPI_LS: R13.2 U7.D9(RPI_LS)
VCC3IO_COSC: C549.1 FB506.2 U7.C15(VCC3IO_COSC)
VCC11A_DDI: C535.1 C538.1 C543.1 C544.1 C548.1 FB505.2 U7.E4(VCC11A_DDI_1) U7.E19(VCC11A_DDI_0) U7.F4(VCC11A_DDI_1) U7.F19(VCC11A_DDI_0)
VCC11A_LVDS: C508.1 C512.1 C515.1 C518.1 C522.1 FB501.2 U7.W11(VCC11A_LVDS) U7.W12(VCC11A_LVDS) U7.W17(VCC11A_LVDS) U7.W18(VCC11A_LVDS)
VCC11AD_PLLD: C555.1 C562.1 FB508.2 U7.D12(VCC11AD_PLLD)
VCC11AD_PLLM: C552.1 C563.1 FB510.2 U7.D13(VCC11AD_PLLM)
VCC18A_LVDS: C48.1 C49.1 C50.1 C545.1 C546.1 C551.1 C553.1 C554.1 C556.1 C558.1 C559.1 FB1.2 U7.B1(VCC18A_LVDS) U7.B22(VCC18A_LVDS) U7.C1(VCC18A_LVDS) U7.C22(VCC18A_LVDS) U7.D2(VCC18A_LVDS) U7.D3(VCC18A_LVDS) U7.D4(VCC18A_LVDS) U7.D5(VCC18A_LVDS) U7.D7(VCC18A_LVDS) U7.D18(VCC18A_LVDS) U7.D19(VCC18A_LVDS) U7.D20(VCC18A_LVDS) U7.D21(VCC18A_LVDS) U7.E20(VCC18A_LVDS)
VCC33A_LVDS: C501.1 C502.1 C507.1 C510.1 C517.1 FB500.2 U7.W9(VCC33A_LVDS) U7.W13(VCC33A_LVDS) U7.W15(VCC33A_LVDS) U7.W19(VCC33A_LVDS) U7.Y9(VCC33A_LVDS) U7.Y13(VCC33A_LVDS) U7.Y15(VCC33A_LVDS) U7.Y19(VCC33A_LVDS)
NetC42_1: C42.1 R18.1 Y1.3

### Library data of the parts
C42 C46 = CMP-0007126-4: CAP, CERM, 15 pF, 50 V, +/- 5%, C0G/NP0, AEC-Q200 Grade 1, 0603; Manufacturer: MuRata; TaMin_C: -55°C; Polarized: N; SizeAreaWB_mm2: 4.68; Value1: Unknown; U/M: EA; Value: 15pF; TaMax_C: 125°C; SizeZ_mm: 1; SizeX_mm: 1.6; SizeY_mm: 0.8; SizeArea_mm2: 1.28; AEC Qualified: Y; AEC Category: Q200
C48 C49 C502-C504 C506-C518 C520 C523-C525 C527-C534 C536-C541 C543-C549 C551-C556 C558 C559 C564 C565 = CMP-0080702-1: as C500 on sheet TIDA-08007_DLPC230Interface
C50 C542 = CMP-0007864-2: CAP, CERM, 10 uF, 10 V, +/- 20%, X7R, 0805; Manufacturer: TDK; TaMin_C: -55°C; Polarized: N; SizeAreaWB_mm2: 6.75; Value1: Unknown; U/M: EA; Value: 10uF; TaMax_C: 125°C; SizeZ_mm: 1.45; SizeX_mm: 2; SizeY_mm: 1.25; Cap_Case: 0805; SizeArea_mm2: 2.5; AEC Category: Q200
C501 C522 C535 = CMP-0064934-4: CAP, CERM, 2.2 uF, 16 V,+/- 10%, X7R, 0603; Manufacturer: Taiyo Yuden; TaMin_C: -55°C; Polarized: N; SizeAreaWB_mm2: 4.68; Value1: Unknown; U/M: EA; Value: 2.2uF; TaMax_C: 125°C; SizeZ_mm: 1; SizeX_mm: 1.6; SizeY_mm: 0.8; SizeArea_mm2: 1.28; AEC Category: Q200
C562 C563 = CMP-0085180-1: CAP, CERM, 1 µF, 16 V,+/- 10%, X7R, AEC-Q200 Grade 1, 0805; Manufacturer: MuRata; AEC Category: Q200; U/M: EA; SizeAreaWB_mm2: 6.75; SizeArea_mm2: 2.5; SizeX_mm: 2; AEC Qualified: Y; Value: 1uF; TaMin_C: -55°C; SizeY_mm: 1.25; Polarized: N; SizeZ_mm: 1.45; TaMax_C: 125°C; Cap_Case: 0805; AEC Grade: 1
FB1 FB500 FB501 FB505 FB507-FB510 = CMP-0086561-1: Ind Chip Bead Multi-Layer 100Ohm 25% 100MHz Ferrite 2.5A 0603 T/R; Manufacturer: Taiyo Yuden; Symbol Name: SYM-FBMH1608HM101-TV; SizeZ_mm: 0.9mm; DCR_ohm: 0.035
FB506 = CMP-0086561-1: Ind Chip Bead Multi-Layer 100Ohm 25% 100MHz Ferrite 2.5A 0603 T/R; PartNumber: FBMH1608HM101-TV; Manufacturer: Taiyo Yuden; Symbol Name: SYM-FBMH1608HM101-TV; SizeZ_mm: 0.9mm; DCR_ohm: 0.035
R12 R13 R503 = CMP-0021712-3: RES, 42.2 k, 1%, 0.125 W, AEC-Q200 Grade 0, 0805; Manufacturer: Panasonic; Power_W: 125mW; TempCo: 100 ppm/C; Value_Code: 42k2; Value: 42.2k; EIA_Code: E96; SizeX_mm: 2; SizeY_mm: 1.25; SizeZ_mm: 1.45; Value2: 0.125W; SizeArea_mm2: 2.5; AEC Qualified: Y; AEC Category: Q200; AEC Grade: 0; SizeAreaWB_mm2: 6.75
R18 = CMP-0021666-2: RES, 3.00 k, 1%, 0.125 W, AEC-Q200 Grade 0, 0805; Manufacturer: Panasonic; Power_W: 125mW; TempCo: 100 ppm/C; Value_Code: 3k00; U/M: EA; Value: 3.00k; Res_ohm: 3k; SizeX_mm: 2; SizeY_mm: 1.25; SizeZ_mm: 1.45; Value2: 0.125W; SizeArea_mm2: 2.5; AEC Qualified: Y; VDC_V: 150V; AEC Grade: 0; AEC Category: Q200
R19 = CMP-0020623-3: RES, 1.0 M, 5%, 0.125 W, AEC-Q200 Grade 0, 0805; Manufacturer: Panasonic; Power_W: 125mW; TempCo: 150 ppm/C; Value_Code: 1M00; Value: 1.0Meg; EIA_Code: E24; Res_ohm: 1M; SizeX_mm: 2; SizeY_mm: 1.25; SizeZ_mm: 1.45; Value2: 0.125W; SizeArea_mm2: 2.5; AEC Qualified: Y; VDC_V: 150V; AEC Category: Q200; AEC Grade: 0; SizeAreaWB_mm2: 6.75
U7 = CMP-0750177-3: as U7 on sheet TIDA-08007_DLPC230Interface
Y1 = CMP-0087311-1: SMD SEAM SEALING X'TAL 3.2×2.5; Manufacturer: TXC Corporation; Load Capacitance: 10pF; AEC Grade: Grade 1; Frequency_Fixed: 16MHz; AEC Qualified: Yes; SizeZ_mm: 0.8mm; Frequency Stability: 50ppm; Frequency Tolerance: 10ppm

## Sheet TIDA-08007_DLPC230GPIO.SchDoc: DLPC230 Configuration and GPIO
size 431 x 279 mm; Date: Not shown in title block; ApprovedBy: Not shown in title block; CheckedBy: Not shown in title block; Author: Not shown in title block; CompanyName: Not shown in title block; DrawnBy: Jake Pulliam; Engineer: Not shown in title block; Organization: Not shown in title block; Address1: Not shown in title block; Address2: Not shown in title block; Address3: Not shown in title block; Address4: Not shown in title block; DocumentNumber: 5; Revision: Use project parameter SCH_Rev; SheetNumber: 5; SheetTotal: 10; PageSetup: Record=PageOptions¦CenterHorizontal=True¦CenterVertical=True¦PrintScale=1.00¦XCorrection=1.00¦YCorrection=1.00¦PrintKind=0¦BorderSize=5000000¦LeftOffset=0¦BottomOffset=0¦Orientation=2¦PaperLength=1000¦PaperWidth=1000¦Scale=100¦PaperSource=15¦PrintQuality=600¦MediaType=1¦DitherType=10¦PaperKind=Letter¦PrintScaleMode=1
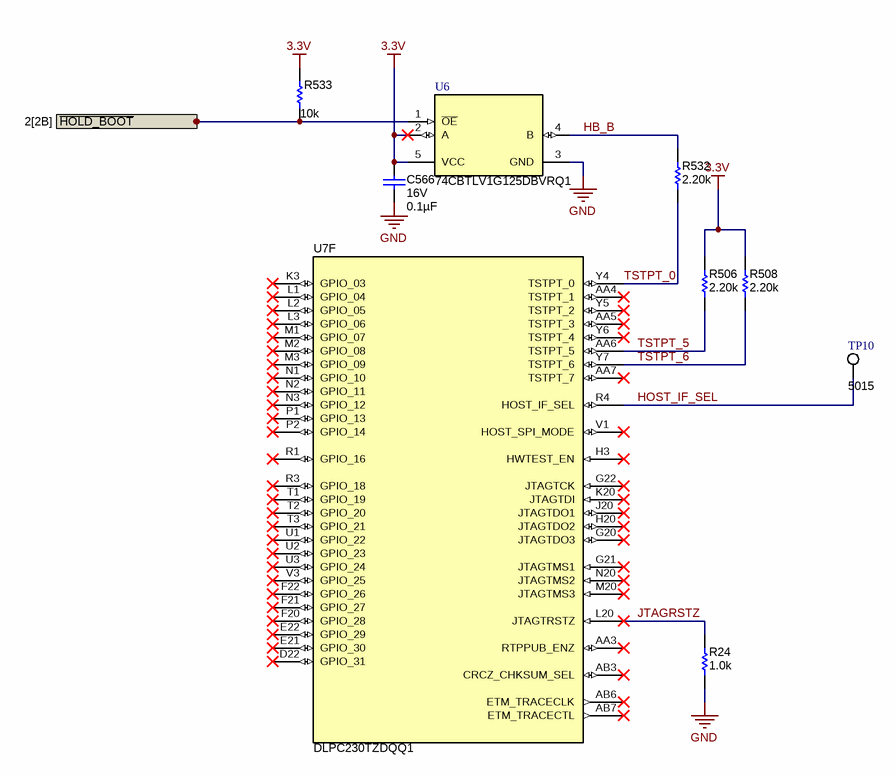
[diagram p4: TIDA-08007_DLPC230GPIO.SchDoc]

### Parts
C566  VDC_V: 16V  ValueDisplayed: 0.1µF  [0402]  (hidden comment: GCM155R71C104JA55D)
R24  ValueDisplayed: 1.0k  [0402]  (hidden comment: ERJ-2GEJ102X)
R506  ValueDisplayed: 2.20k  [0402]  (hidden comment: ERJ-2RKF2201X)
R508  ValueDisplayed: 2.20k  [0402]  (hidden comment: ERJ-2RKF2201X)
R532  ValueDisplayed: 2.20k  [0402]  (hidden comment: ERJ-2RKF2201X)
R533  ValueDisplayed: 10k  [0402]  (hidden comment: ERJ-2GEJ103X)
TP10  5015  [Testpoint_Keystone_Miniature]
U6  74CBTLV1G125DBVRQ1  [DBV0005A_N]
U7  DLPC230TZDQQ1  [ZDQ0324]  (part F of 9)

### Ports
~{HOLD_BOOT} (in, see 2[2B])

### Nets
3.3V: C566.1 R506.2 R508.2 R533.2 U6.2(A) U6.5(VCC)
GND: C566.2 R24.1 U6.3(GND)
~{HOLD_BOOT}: R533.1 U6.1(~{OE}) ; port ~{HOLD_BOOT}
HB_B: R532.2 U6.4(B)
HOST_IF_SEL: TP10.1 U7.R4(HOST_IF_SEL)
JTAGRSTZ: R24.2 U7.L20(JTAGTRSTZ)
TSTPT_0: R532.1 U7.Y4(TSTPT_0)
TSTPT_5: R506.1 U7.AA6(TSTPT_5)
TSTPT_6: R508.1 U7.Y7(TSTPT_6)

Not connected (* = marked no-connect by the designer): U7 AA3(RTPPUB_ENZ)* AA4(TSTPT_1)* AA5(TSTPT_3)* AA7(TSTPT_7)* AB3(CRCZ_CHKSUM_SEL)* AB6(ETM_TRACECLK)* AB7(ETM_TRACECTL)* D22(GPIO_31)* E21(GPIO_30)* E22(GPIO_29)* F20(GPIO_28)* F21(GPIO_27)* F22(GPIO_26)* G20(JTAGTDO3)* G21(JTAGTMS1)* G22(JTAGTCK)* H3(HWTEST_EN)* H20(JTAGTDO2)* J20(JTAGTDO1)* K3(GPIO_03)* K20(JTAGTDI)* L1(GPIO_04)* L2(GPIO_05)* L3(GPIO_06)* M1(GPIO_07)* M2(GPIO_08)* M3(GPIO_09)* M20(JTAGTMS3)* N1(GPIO_10)* N2(GPIO_11)* N3(GPIO_12)* N20(JTAGTMS2)* P1(GPIO_13)* P2(GPIO_14)* R1(GPIO_16)* R3(GPIO_18)* T1(GPIO_19)* T2(GPIO_20)* T3(GPIO_21)* U1(GPIO_22)* U2(GPIO_23)* U3(GPIO_24)* V1(HOST_SPI_MODE)* V3(GPIO_25)* Y5(TSTPT_2)* Y6(TSTPT_4)*

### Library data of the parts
C566 = CMP-0080702-1: as C500 on sheet TIDA-08007_DLPC230Interface
R24 = CMP-0078193-1: as R15 on sheet TIDA-08007_DLPC230Interface
R506 R508 R532 = CMP-0026681-1: as R17 on sheet TIDA-08007_DLPC230Interface
R533 = CMP-0026994-4: as R501 on sheet TIDA-08007_DLPC230Interface
TP10 = CMP-0055152-1: Test Point, Miniature, SMT; Manufacturer: Keystone; CNHeader: FALSE; Green_Lifecycle: Active; Green_REACh: Passed; CT: TRUE
U6 = CMP-0050954-2: Automotive Catalog Low-Voltage Single FET Bus Switch, DBV0005A (SOT-23-5); Generic Part Number: SN74CBTLV1G125-Q1; Manufacturer: Texas Instruments; Bits(#): 1; Schmitt Trigger: No; VCC(Min)(V): 2.3; Input Type: LV-CMOS; Switch Configuration: SPST; Output Type: CMOS; F @ Nom Voltage(Max)(Mhz): 200; VCC(Max)(V): 3.6; tpd @ Nom Voltage(Max)(ns): 0.25; Logic: True; ICC @ Nom Voltage(Max)(mA): 0.01; Voltage(Nom)(V): 3.3; AEC Category: Q200; AEC Qualified: Y; CompType: IC; SizeAreaWB_mm2: 14.82; SizeArea_mm2: 8.12; SizeX_mm: 2.8; SizeY_mm: 2.9; SizeZ_mm: 1.45
U7 = CMP-0750177-3: as U7 on sheet TIDA-08007_DLPC230Interface

## Sheet TIDA-08007_DMDInterface.SchDoc: DLPC230 / DLP5531 Interface
size 431 x 279 mm; Date: Not shown in title block; ApprovedBy: Not shown in title block; CheckedBy: Not shown in title block; Author: Not shown in title block; CompanyName: Not shown in title block; DrawnBy: Jake Pulliam; Engineer: Not shown in title block; Organization: Not shown in title block; Address1: Not shown in title block; Address2: Not shown in title block; Address3: Not shown in title block; Address4: Not shown in title block; DocumentNumber: 6; Revision: Use project parameter SCH_Rev; SheetNumber: 6; SheetTotal: 10; PageSetup: Record=PageOptions¦CenterHorizontal=True¦CenterVertical=True¦PrintScale=1.00¦XCorrection=1.00¦YCorrection=1.00¦PrintKind=0¦BorderSize=5000000¦LeftOffset=0¦BottomOffset=0¦Orientation=2¦PaperLength=1000¦PaperWidth=1000¦Scale=100¦PaperSource=15¦PrintQuality=600¦MediaType=1¦DitherType=10¦PaperKind=Letter¦PrintScaleMode=1
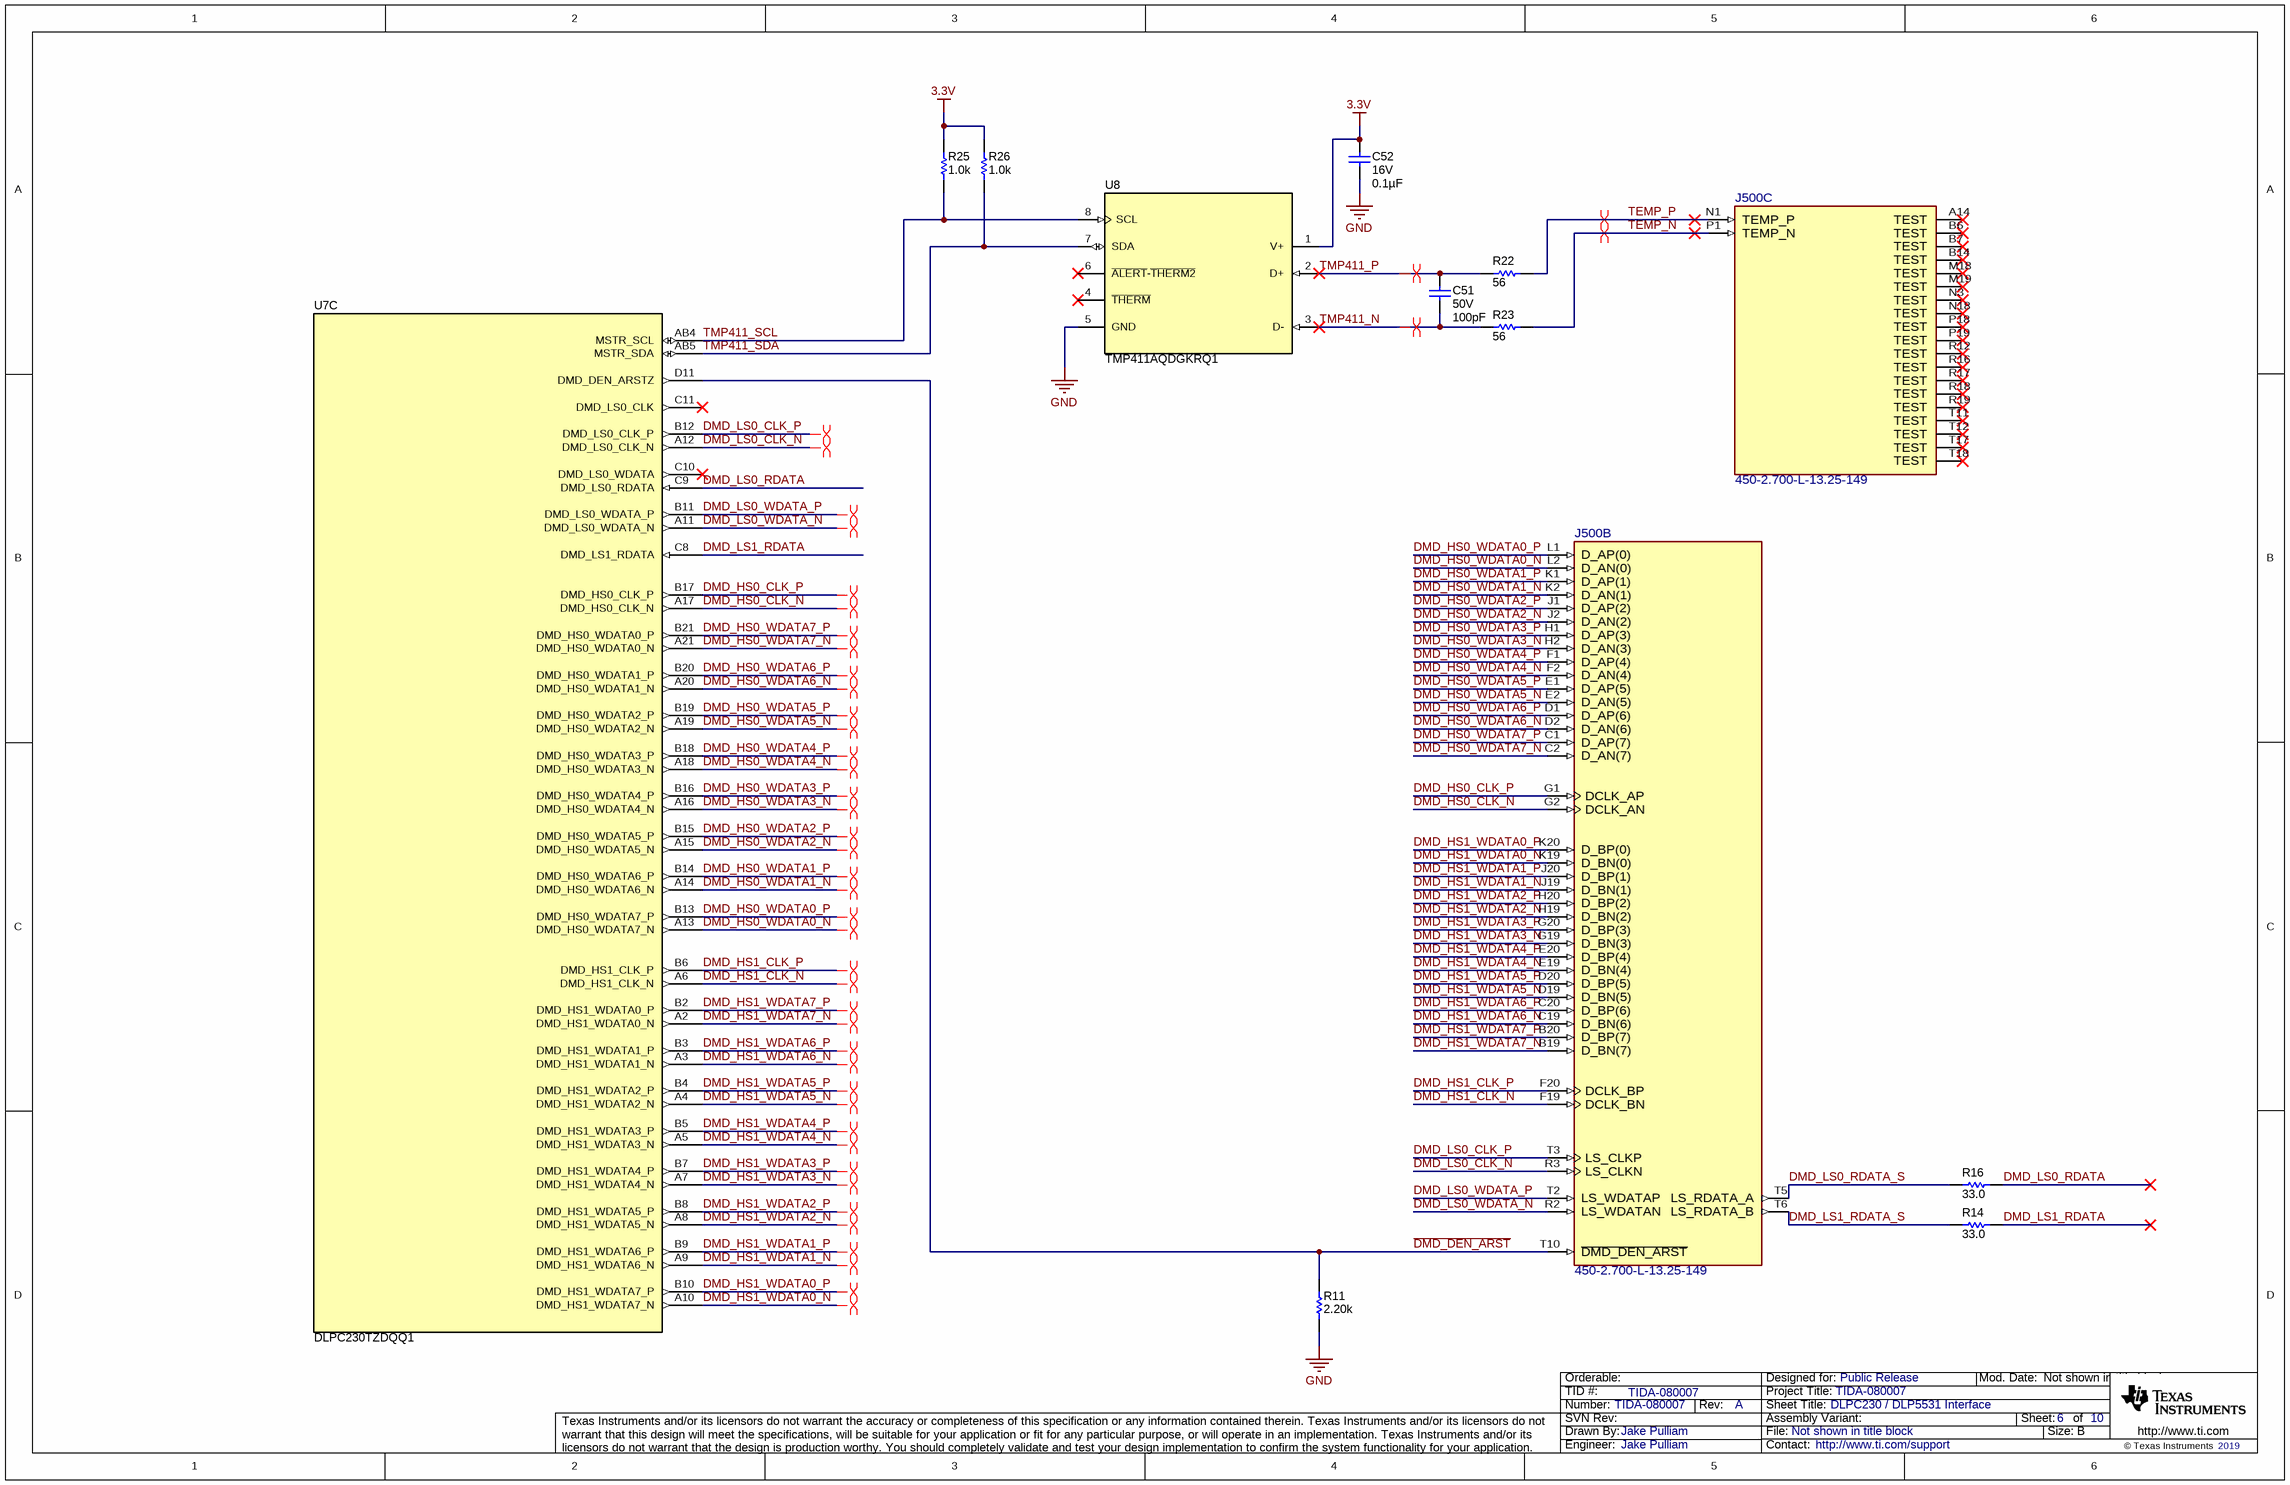
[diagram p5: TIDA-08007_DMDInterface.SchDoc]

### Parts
C51  VDC_V: 50V  ValueDisplayed: 100pF  [0402]  (hidden comment: CGA2B2C0G1H101J050BA)
C52  VDC_V: 16V  ValueDisplayed: 0.1µF  [0402]  (hidden comment: GCM155R71C104JA55D)
J500  450-2.700-L-13.25-149  [FP-450-2.700-L-13.25-149_SOCKET_CPGA149-MFG]  (parts B,C of 3)
R11  ValueDisplayed: 2.20k  [0402]  (hidden comment: ERJ-2RKF2201X)
R14  ValueDisplayed: 33.0  [0402]  (hidden comment: ERJ-2RKF33R0X)
R16  ValueDisplayed: 33.0  [0402]  (hidden comment: ERJ-2RKF33R0X)
R22  ValueDisplayed: 56  [0805_HV]  (hidden comment: ERJ-6GEYJ560V)
R23  ValueDisplayed: 56  [0805_HV]  (hidden comment: ERJ-6GEYJ560V)
R25  ValueDisplayed: 1.0k  [0402]  (hidden comment: ERJ-2GEJ102X)
R26  ValueDisplayed: 1.0k  [0402]  (hidden comment: ERJ-2GEJ102X)
U7  DLPC230TZDQQ1  [ZDQ0324]  (part C of 9)
U8  TMP411AQDGKRQ1  [DGK0008A_L]

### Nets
3.3V: C52.1 R25.2 R26.2 U8.1(V+)
GND: C52.2 R11.1 U8.5(GND)
~{DMD_DEN_ARST}: J500.T10(~{DMD_DEN_ARST}) R11.2 U7.D11(DMD_DEN_ARSTZ)
DMD_HS0_CLK_N: J500.G2(DCLK_AN) U7.A17(DMD_HS0_CLK_N)
DMD_HS0_CLK_P: J500.G1(DCLK_AP) U7.B17(DMD_HS0_CLK_P)
DMD_HS0_WDATA0_N: J500.L2(D_AN(0)) U7.A13(DMD_HS0_WDATA7_N)
DMD_HS0_WDATA0_P: J500.L1(D_AP(0)) U7.B13(DMD_HS0_WDATA7_P)
DMD_HS0_WDATA1_N: J500.K2(D_AN(1)) U7.A14(DMD_HS0_WDATA6_N)
DMD_HS0_WDATA1_P: J500.K1(D_AP(1)) U7.B14(DMD_HS0_WDATA6_P)
DMD_HS0_WDATA2_N: J500.J2(D_AN(2)) U7.A15(DMD_HS0_WDATA5_N)
DMD_HS0_WDATA2_P: J500.J1(D_AP(2)) U7.B15(DMD_HS0_WDATA5_P)
DMD_HS0_WDATA3_N: J500.H2(D_AN(3)) U7.A16(DMD_HS0_WDATA4_N)
DMD_HS0_WDATA3_P: J500.H1(D_AP(3)) U7.B16(DMD_HS0_WDATA4_P)
DMD_HS0_WDATA4_N: J500.F2(D_AN(4)) U7.A18(DMD_HS0_WDATA3_N)
DMD_HS0_WDATA4_P: J500.F1(D_AP(4)) U7.B18(DMD_HS0_WDATA3_P)
DMD_HS0_WDATA5_N: J500.E2(D_AN(5)) U7.A19(DMD_HS0_WDATA2_N)
DMD_HS0_WDATA5_P: J500.E1(D_AP(5)) U7.B19(DMD_HS0_WDATA2_P)
DMD_HS0_WDATA6_N: J500.D2(D_AN(6)) U7.A20(DMD_HS0_WDATA1_N)
DMD_HS0_WDATA6_P: J500.D1(D_AP(6)) U7.B20(DMD_HS0_WDATA1_P)
DMD_HS0_WDATA7_N: J500.C2(D_AN(7)) U7.A21(DMD_HS0_WDATA0_N)
DMD_HS0_WDATA7_P: J500.C1(D_AP(7)) U7.B21(DMD_HS0_WDATA0_P)
DMD_HS1_CLK_N: J500.F19(DCLK_BN) U7.A6(DMD_HS1_CLK_N)
DMD_HS1_CLK_P: J500.F20(DCLK_BP) U7.B6(DMD_HS1_CLK_P)
DMD_HS1_WDATA0_N: J500.K19(D_BN(0)) U7.A10(DMD_HS1_WDATA7_N)
DMD_HS1_WDATA0_P: J500.K20(D_BP(0)) U7.B10(DMD_HS1_WDATA7_P)
DMD_HS1_WDATA1_N: J500.J19(D_BN(1)) U7.A9(DMD_HS1_WDATA6_N)
DMD_HS1_WDATA1_P: J500.J20(D_BP(1)) U7.B9(DMD_HS1_WDATA6_P)
DMD_HS1_WDATA2_N: J500.H19(D_BN(2)) U7.A8(DMD_HS1_WDATA5_N)
DMD_HS1_WDATA2_P: J500.H20(D_BP(2)) U7.B8(DMD_HS1_WDATA5_P)
DMD_HS1_WDATA3_N: J500.G19(D_BN(3)) U7.A7(DMD_HS1_WDATA4_N)
DMD_HS1_WDATA3_P: J500.G20(D_BP(3)) U7.B7(DMD_HS1_WDATA4_P)
DMD_HS1_WDATA4_N: J500.E19(D_BN(4)) U7.A5(DMD_HS1_WDATA3_N)
DMD_HS1_WDATA4_P: J500.E20(D_BP(4)) U7.B5(DMD_HS1_WDATA3_P)
DMD_HS1_WDATA5_N: J500.D19(D_BN(5)) U7.A4(DMD_HS1_WDATA2_N)
DMD_HS1_WDATA5_P: J500.D20(D_BP(5)) U7.B4(DMD_HS1_WDATA2_P)
DMD_HS1_WDATA6_N: J500.C19(D_BN(6)) U7.A3(DMD_HS1_WDATA1_N)
DMD_HS1_WDATA6_P: J500.C20(D_BP(6)) U7.B3(DMD_HS1_WDATA1_P)
DMD_HS1_WDATA7_N: J500.B19(D_BN(7)) U7.A2(DMD_HS1_WDATA0_N)
DMD_HS1_WDATA7_P: J500.B20(D_BP(7)) U7.B2(DMD_HS1_WDATA0_P)
DMD_LS0_CLK_N: J500.R3(LS_CLKN) U7.A12(DMD_LS0_CLK_N)
DMD_LS0_CLK_P: J500.T3(LS_CLKP) U7.B12(DMD_LS0_CLK_P)
DMD_LS0_RDATA: R16.2 U7.C9(DMD_LS0_RDATA)
DMD_LS0_RDATA_S: J500.T5(LS_RDATA_A) R16.1
DMD_LS0_WDATA_N: J500.R2(LS_WDATAN) U7.A11(DMD_LS0_WDATA_N)
DMD_LS0_WDATA_P: J500.T2(LS_WDATAP) U7.B11(DMD_LS0_WDATA_P)
DMD_LS1_RDATA: R14.2 U7.C8(DMD_LS1_RDATA)
DMD_LS1_RDATA_S: J500.T6(LS_RDATA_B) R14.1
TEMP_N: J500.P1(TEMP_N) R23.2
TEMP_P: J500.N1(TEMP_P) R22.2
TMP411_N: C51.2 R23.1 U8.3(D-)
TMP411_P: C51.1 R22.1 U8.2(D+)
TMP411_SCL: R25.1 U7.AB4(MSTR_SCL) U8.8(SCL)
TMP411_SDA: R26.1 U7.AB5(MSTR_SDA) U8.7(SDA)

Not connected (* = marked no-connect by the designer): J500 A14(TEST)* B6(TEST)* B7(TEST)* B14(TEST)* M18(TEST)* M19(TEST)* N3(TEST)* N18(TEST)* P18(TEST)* P19(TEST)* R12(TEST)* R16(TEST)* R17(TEST)* R18(TEST)* R19(TEST)* T11(TEST)* T12(TEST)* T17(TEST)* T18(TEST)*; U7 C10(DMD_LS0_WDATA)* C11(DMD_LS0_CLK)*; U8 4(~{THERM})* 6(~{ALERT}-~{THERM2})*

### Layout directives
differential pair: DMD_HS0_CLK_N, DMD_HS0_CLK_P, DMD_HS0_WDATA0_N, DMD_HS0_WDATA0_P, DMD_HS0_WDATA1_N, DMD_HS0_WDATA1_P, DMD_HS0_WDATA2_N, DMD_HS0_WDATA2_P, DMD_HS0_WDATA3_N, DMD_HS0_WDATA3_P, DMD_HS0_WDATA4_N, DMD_HS0_WDATA4_P, DMD_HS0_WDATA5_N, DMD_HS0_WDATA5_P, DMD_HS0_WDATA6_N, DMD_HS0_WDATA6_P, DMD_HS0_WDATA7_N, DMD_HS0_WDATA7_P, DMD_HS1_CLK_N, DMD_HS1_CLK_P, DMD_HS1_WDATA0_N, DMD_HS1_WDATA0_P, DMD_HS1_WDATA1_N, DMD_HS1_WDATA1_P, DMD_HS1_WDATA2_N, DMD_HS1_WDATA2_P, DMD_HS1_WDATA3_N, DMD_HS1_WDATA3_P, DMD_HS1_WDATA4_N, DMD_HS1_WDATA4_P, DMD_HS1_WDATA5_N, DMD_HS1_WDATA5_P, DMD_HS1_WDATA6_N, DMD_HS1_WDATA6_P, DMD_HS1_WDATA7_N, DMD_HS1_WDATA7_P, DMD_LS0_CLK_N, DMD_LS0_CLK_P, DMD_LS0_WDATA_N, DMD_LS0_WDATA_P, TEMP_N, TEMP_P, TMP411_N, TMP411_P

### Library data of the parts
C51 = CMP-0006308-2: CAP, CERM, 100 pF, 50 V, +/- 5%, C0G/NP0, AEC-Q200 Grade 1, 0402; Manufacturer: TDK; TaMin_C: -55°C; Polarized: N; SizeAreaWB_mm2: 3; Value1: Unknown; U/M: EA; Value: 100pF; TaMax_C: 125°C; SizeZ_mm: 0.6; SizeX_mm: 1; SizeY_mm: 0.5; AEC Qualified: Y; AEC Category: Q200
C52 = CMP-0080702-1: as C500 on sheet TIDA-08007_DLPC230Interface
J500 = CMP-0087054-2: Socket Assembly for DLP5531; Manufacturer: Texas Instruments; DUT-Pitch_mm: 1.27mm; SizeZ_mm: 2.9mm; DUT-PIN: 149; DUT-PackageType: CPGA149
R11 = CMP-0026681-1: as R17 on sheet TIDA-08007_DLPC230Interface
R14 R16 = CMP-0026696-1: as R512 on sheet TIDA-08007_DLPC230Interface
R22 R23 = CMP-0020744-3: RES, 56, 5%, 0.125 W, AEC-Q200 Grade 0, 0805; Manufacturer: Panasonic; Power_W: 125mW; TempCo: 200 ppm/C; Value_Code: 56R0; Value: 56; EIA_Code: E24; SizeX_mm: 2; SizeY_mm: 1.25; SizeZ_mm: 1.45; Value2: 0.125W; SizeArea_mm2: 2.5; AEC Qualified: Y; VDC_V: 150V; AEC Category: Q200; AEC Grade: 0; SizeAreaWB_mm2: 6.75
R25 R26 = CMP-0078193-1: as R15 on sheet TIDA-08007_DLPC230Interface
U7 = CMP-0750177-3: DLP® Automotive DMD Controller for DLP553x-Q1 Chipset, ZDQ0324 (BGA-324); Manufacturer: Texas Instruments; SizeZ_mm: 2.352; AEC Category: Q200; AEC Qualified: Y; SizeAreaWB_mm2: 625; CompType: IC; SizeArea_mm2: 529; SizeX_mm: 23
U8 = CMP-0860146-1: Automotive Grade, Remote and Local Temperature Sensor with N-Factor and Series-R Correction, DGK0008A (VSSOP-8); Alternate Manufacturer: Texas Instruments; SizeAreaWB_mm2: 23.6; SizeArea_mm2: 14.7; SizeX_mm: 4.9; AEC Category: Q200; SizeZ_mm: 1.1; CompType: IC; AEC Qualified: Y; SizeY_mm: 3

## Sheet TIDA-08007_DMDPower.SchDoc: DLP5531 Power
size 431 x 279 mm; Date: Not shown in title block; ApprovedBy: Not shown in title block; CheckedBy: Not shown in title block; Author: Not shown in title block; CompanyName: Not shown in title block; DrawnBy: Jake Pulliam; Engineer: Not shown in title block; Organization: Not shown in title block; Address1: Not shown in title block; Address2: Not shown in title block; Address3: Not shown in title block; Address4: Not shown in title block; DocumentNumber: 7; Revision: Use project parameter SCH_Rev; SheetNumber: 7; SheetTotal: 10; PageSetup: Record=PageOptions¦CenterHorizontal=True¦CenterVertical=True¦PrintScale=1.00¦XCorrection=1.00¦YCorrection=1.00¦PrintKind=0¦BorderSize=5000000¦LeftOffset=0¦BottomOffset=0¦Orientation=2¦PaperLength=1000¦PaperWidth=1000¦Scale=100¦PaperSource=15¦PrintQuality=600¦MediaType=1¦DitherType=10¦PaperKind=Letter¦PrintScaleMode=1
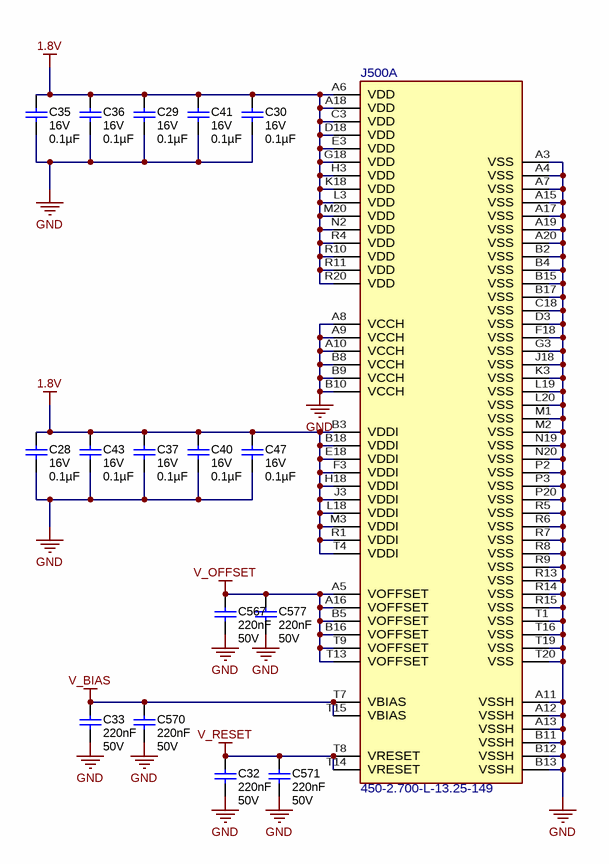
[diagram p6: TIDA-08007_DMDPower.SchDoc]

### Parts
C28  VDC_V: 16V  ValueDisplayed: 0.1µF  [0402]  (hidden comment: GCM155R71C104JA55D)
C29  VDC_V: 16V  ValueDisplayed: 0.1µF  [0402]  (hidden comment: GCM155R71C104JA55D)
C30  VDC_V: 16V  ValueDisplayed: 0.1µF  [0402]  (hidden comment: GCM155R71C104JA55D)
C32  Cap_F: 220nF  VDC_V: 50V  [0603]  (hidden comment: GCM188R71H224KA64D)
C33  Cap_F: 220nF  VDC_V: 50V  [0603]  (hidden comment: GCM188R71H224KA64D)
C35  VDC_V: 16V  ValueDisplayed: 0.1µF  [0402]  (hidden comment: GCM155R71C104JA55D)
C36  VDC_V: 16V  ValueDisplayed: 0.1µF  [0402]  (hidden comment: GCM155R71C104JA55D)
C37  VDC_V: 16V  ValueDisplayed: 0.1µF  [0402]  (hidden comment: GCM155R71C104JA55D)
C40  VDC_V: 16V  ValueDisplayed: 0.1µF  [0402]  (hidden comment: GCM155R71C104JA55D)
C41  VDC_V: 16V  ValueDisplayed: 0.1µF  [0402]  (hidden comment: GCM155R71C104JA55D)
C43  VDC_V: 16V  ValueDisplayed: 0.1µF  [0402]  (hidden comment: GCM155R71C104JA55D)
C47  VDC_V: 16V  ValueDisplayed: 0.1µF  [0402]  (hidden comment: GCM155R71C104JA55D)
C567  Cap_F: 220nF  VDC_V: 50V  [0603]  (hidden comment: GCM188R71H224KA64D)
C570  Cap_F: 220nF  VDC_V: 50V  [0603]  (hidden comment: GCM188R71H224KA64D)
C571  Cap_F: 220nF  VDC_V: 50V  [0603]  (hidden comment: GCM188R71H224KA64D)
C577  Cap_F: 220nF  VDC_V: 50V  [0603]  (hidden comment: GCM188R71H224KA64D)
J500  450-2.700-L-13.25-149  [FP-450-2.700-L-13.25-149_SOCKET_CPGA149-MFG]  (part A of 3)

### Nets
1.8V: C28.1 C29.1 C30.1 C35.1 C36.1 C37.1 C40.1 C41.1 C43.1 C47.1 J500.A6(VDD) J500.A18(VDD) J500.B3(VDDI) J500.B18(VDDI) J500.C3(VDD) J500.D18(VDD) J500.E3(VDD) J500.E18(VDDI) J500.F3(VDDI) J500.G18(VDD) J500.H3(VDD) J500.H18(VDDI) J500.J3(VDDI) J500.K18(VDD) J500.L3(VDD) J500.L18(VDDI) J500.M3(VDDI) J500.M20(VDD) J500.N2(VDD) J500.R1(VDDI) J500.R4(VDD) J500.R10(VDD) J500.R11(VDD) J500.R20(VDD) J500.T4(VDDI)
GND: C28.2 C29.2 C30.2 C32.2 C33.2 C35.2 C36.2 C37.2 C40.2 C41.2 C43.2 C47.2 C567.2 C570.2 C571.2 C577.2 J500.A3(VSS) J500.A4(VSS) J500.A7(VSS) J500.A8(VCCH) J500.A9(VCCH) J500.A10(VCCH) J500.A11(VSSH) J500.A12(VSSH) J500.A13(VSSH) J500.A15(VSS) J500.A17(VSS) J500.A19(VSS) J500.A20(VSS) J500.B2(VSS) J500.B4(VSS) J500.B8(VCCH) J500.B9(VCCH) J500.B10(VCCH) J500.B11(VSSH) J500.B12(VSSH) J500.B13(VSSH) J500.B15(VSS) J500.B17(VSS) J500.C18(VSS) J500.D3(VSS) J500.F18(VSS) J500.G3(VSS) J500.J18(VSS) J500.K3(VSS) J500.L19(VSS) J500.L20(VSS) J500.M1(VSS) J500.M2(VSS) J500.N19(VSS) J500.N20(VSS) J500.P2(VSS) J500.P3(VSS) J500.P20(VSS) J500.R5(VSS) J500.R6(VSS) J500.R7(VSS) J500.R8(VSS) J500.R9(VSS) J500.R13(VSS) J500.R14(VSS) J500.R15(VSS) J500.T1(VSS) J500.T16(VSS) J500.T19(VSS) J500.T20(VSS)
V_BIAS: C33.1 C570.1 J500.T7(VBIAS) J500.T15(VBIAS)
V_OFFSET: C567.1 C577.1 J500.A5(VOFFSET) J500.A16(VOFFSET) J500.B5(VOFFSET) J500.B16(VOFFSET) J500.T9(VOFFSET) J500.T13(VOFFSET)
V_RESET: C32.1 C571.1 J500.T8(VRESET) J500.T14(VRESET)

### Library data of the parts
C28-C30 C35-C37 C40 C41 C43 C47 = CMP-0080702-1: as C500 on sheet TIDA-08007_DLPC230Interface
C32 C33 C567 C570 C571 C577 = CMP-0007145-4: CAP, CERM, 0.22 uF, 50 V, +/- 10%, X7R, AEC-Q200 Grade 1, 0603; Manufacturer: MuRata; TaMin_C: -55°C; Polarized: N; SizeAreaWB_mm2: 4.68; Value1: Unknown; U/M: EA; Value: 0.22uF; TaMax_C: 125°C; SizeZ_mm: 1; SizeX_mm: 1.6; SizeY_mm: 0.8; SizeArea_mm2: 1.28; AEC Qualified: Y; AEC Category: Q200
J500 = CMP-0087054-2: as J500 on sheet TIDA-08007_DMDInterface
